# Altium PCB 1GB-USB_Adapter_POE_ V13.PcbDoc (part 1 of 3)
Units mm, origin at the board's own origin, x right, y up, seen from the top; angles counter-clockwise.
Board outline 92 x 80 mm, 4 copper layers (Top Layer, Signal Layer 2, Signal Layer 3, Bottom Layer), stack 1.57 mm thick; 189 components, 102 nets, 551 pads, 429 vias.
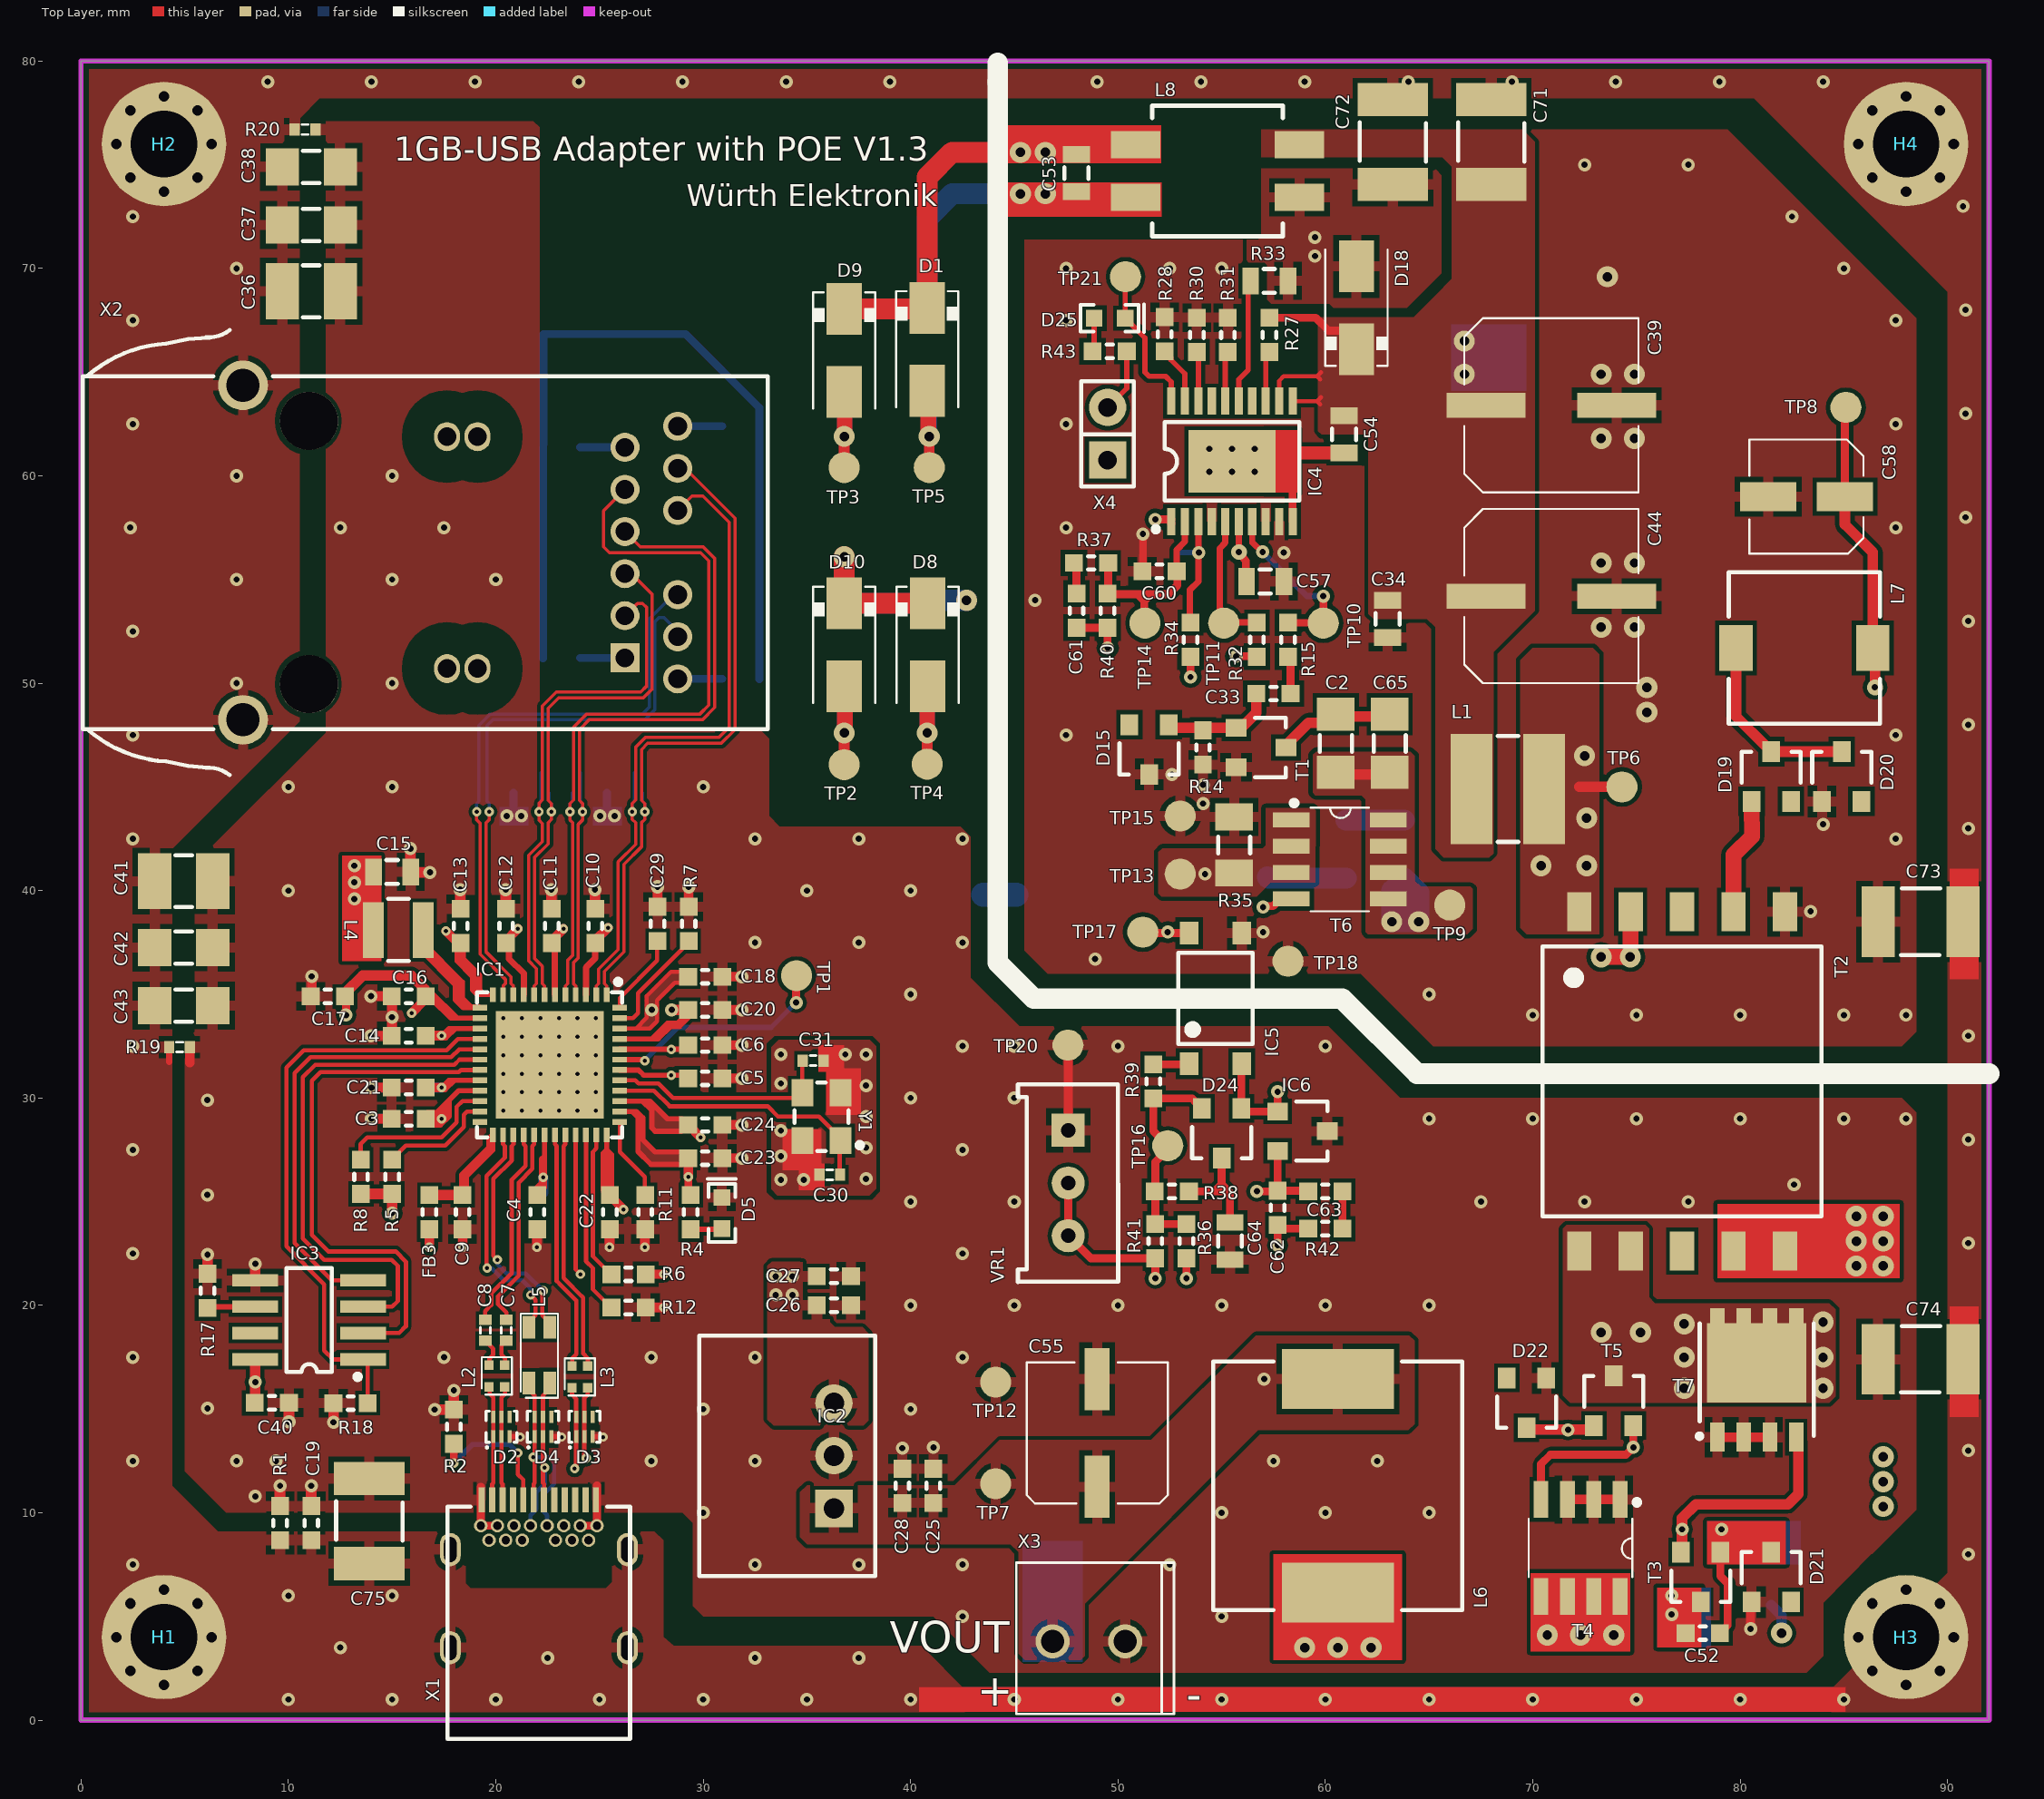
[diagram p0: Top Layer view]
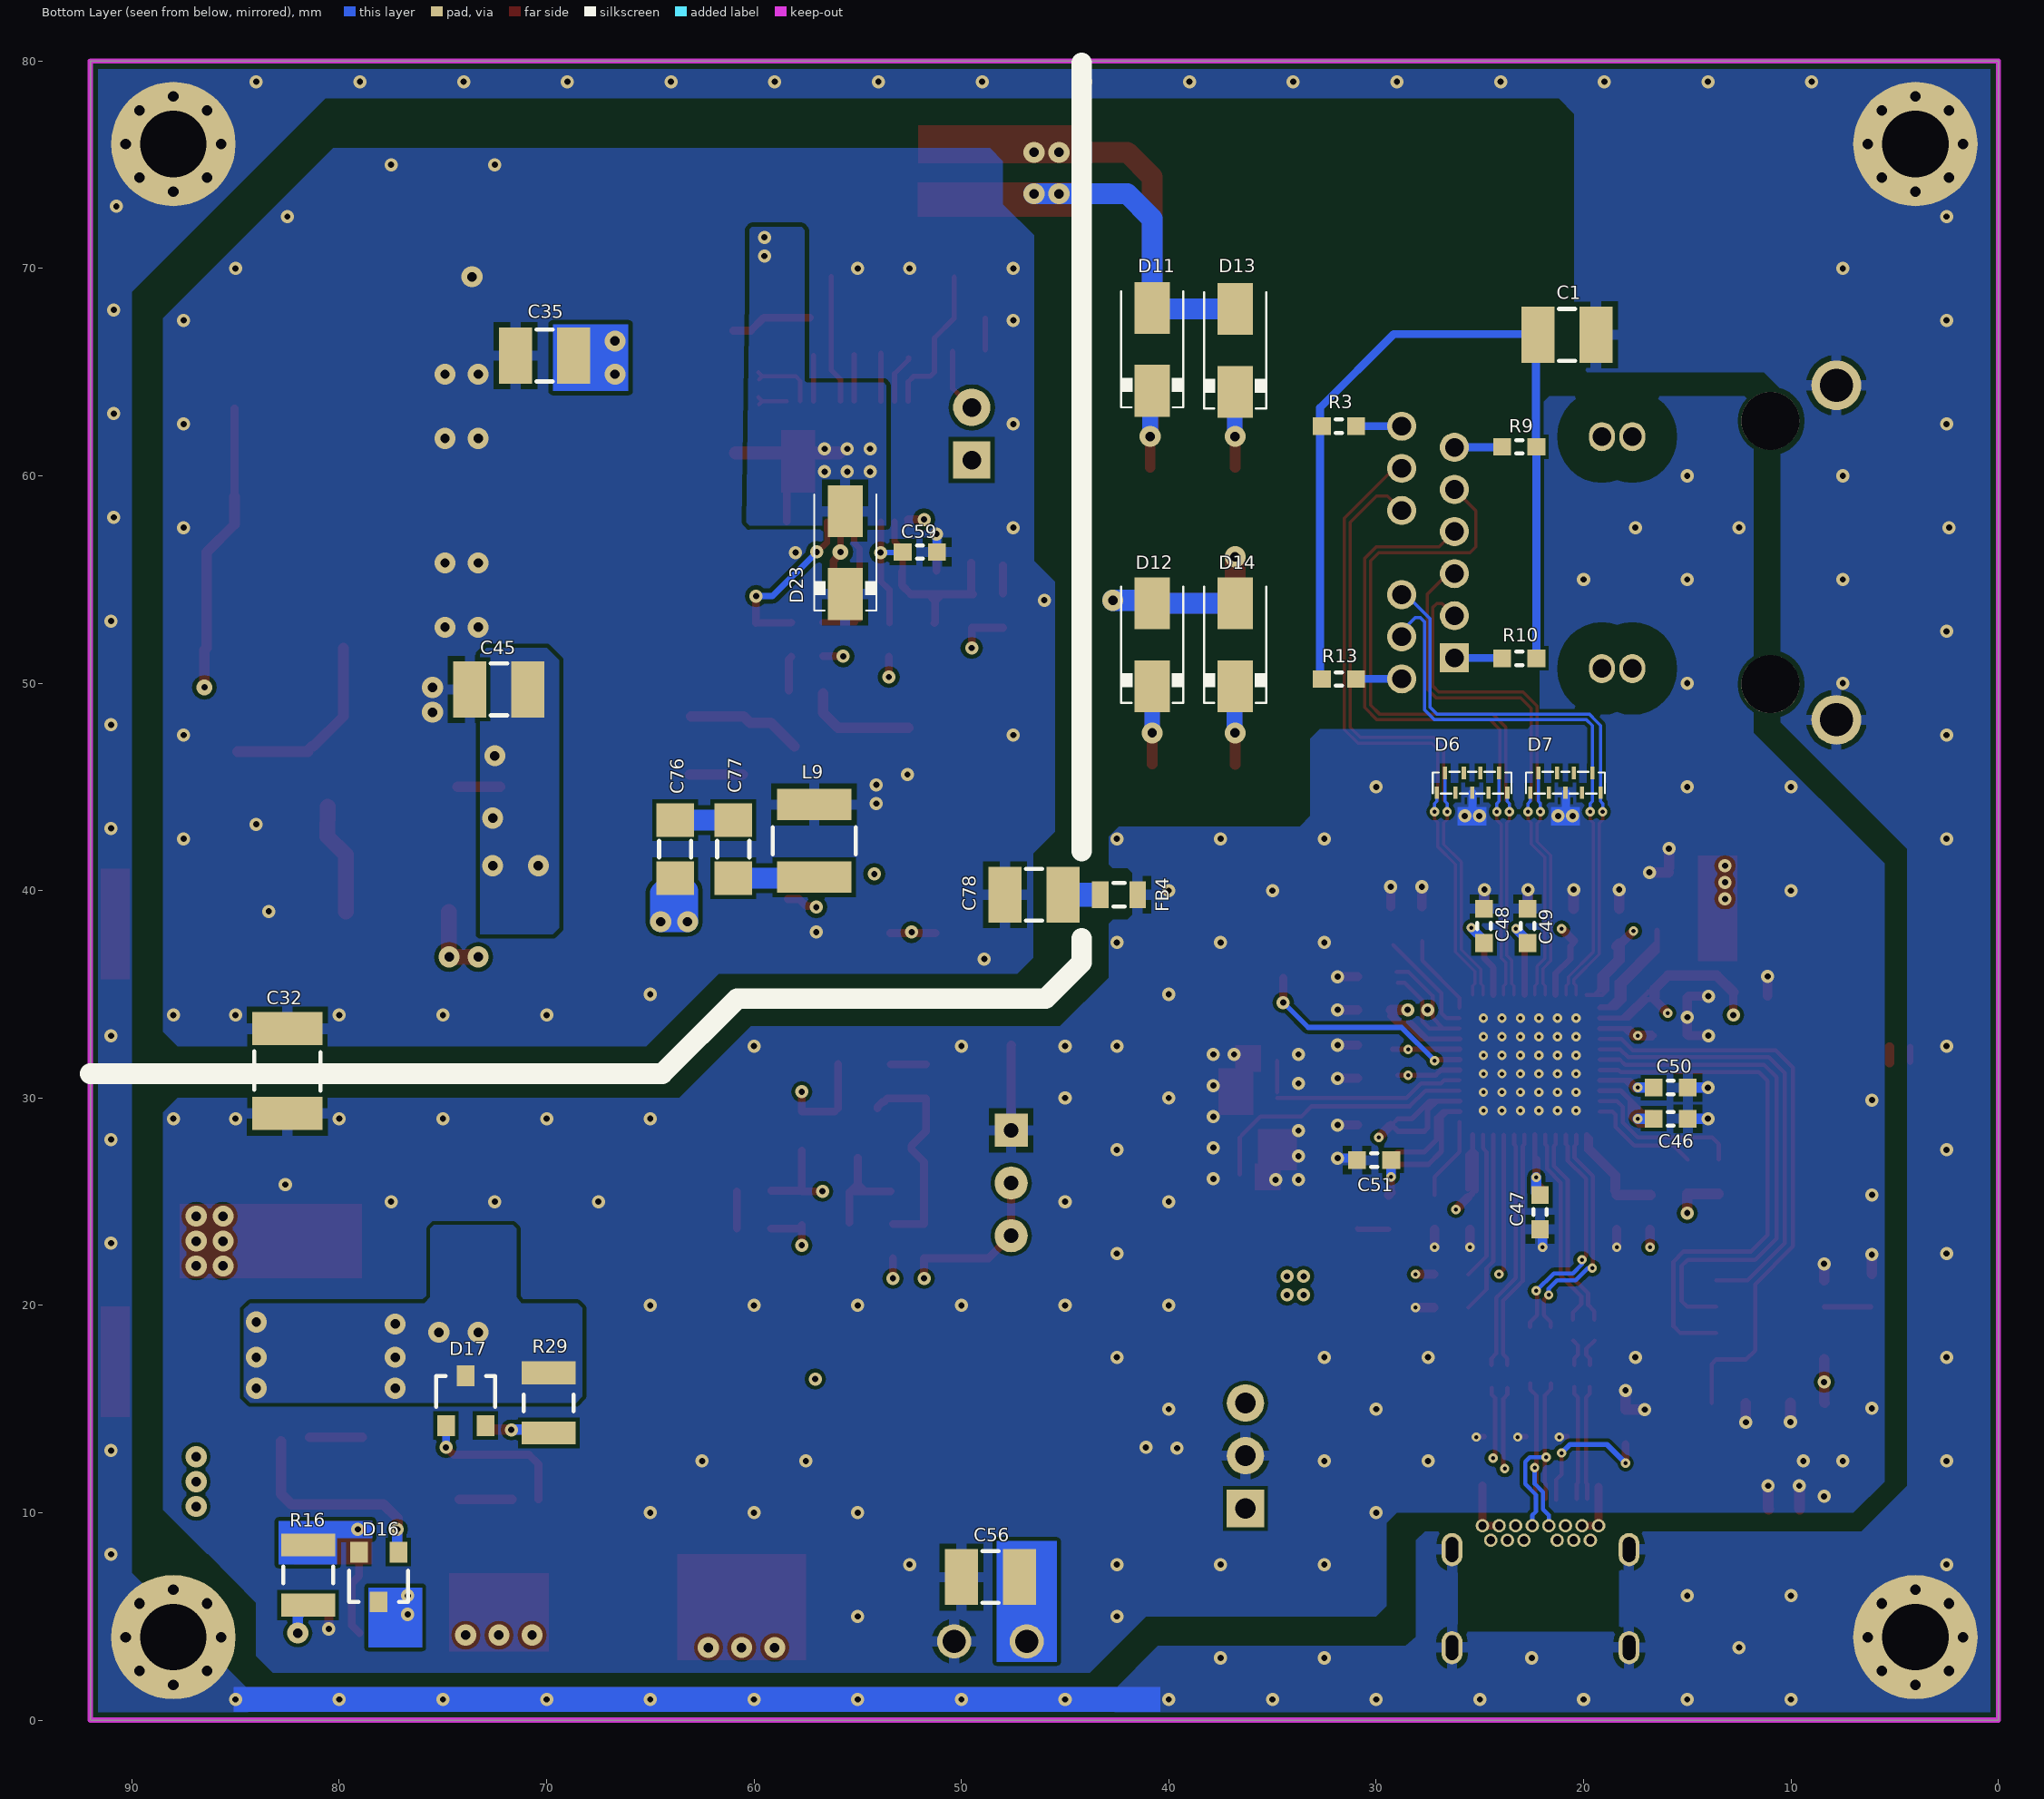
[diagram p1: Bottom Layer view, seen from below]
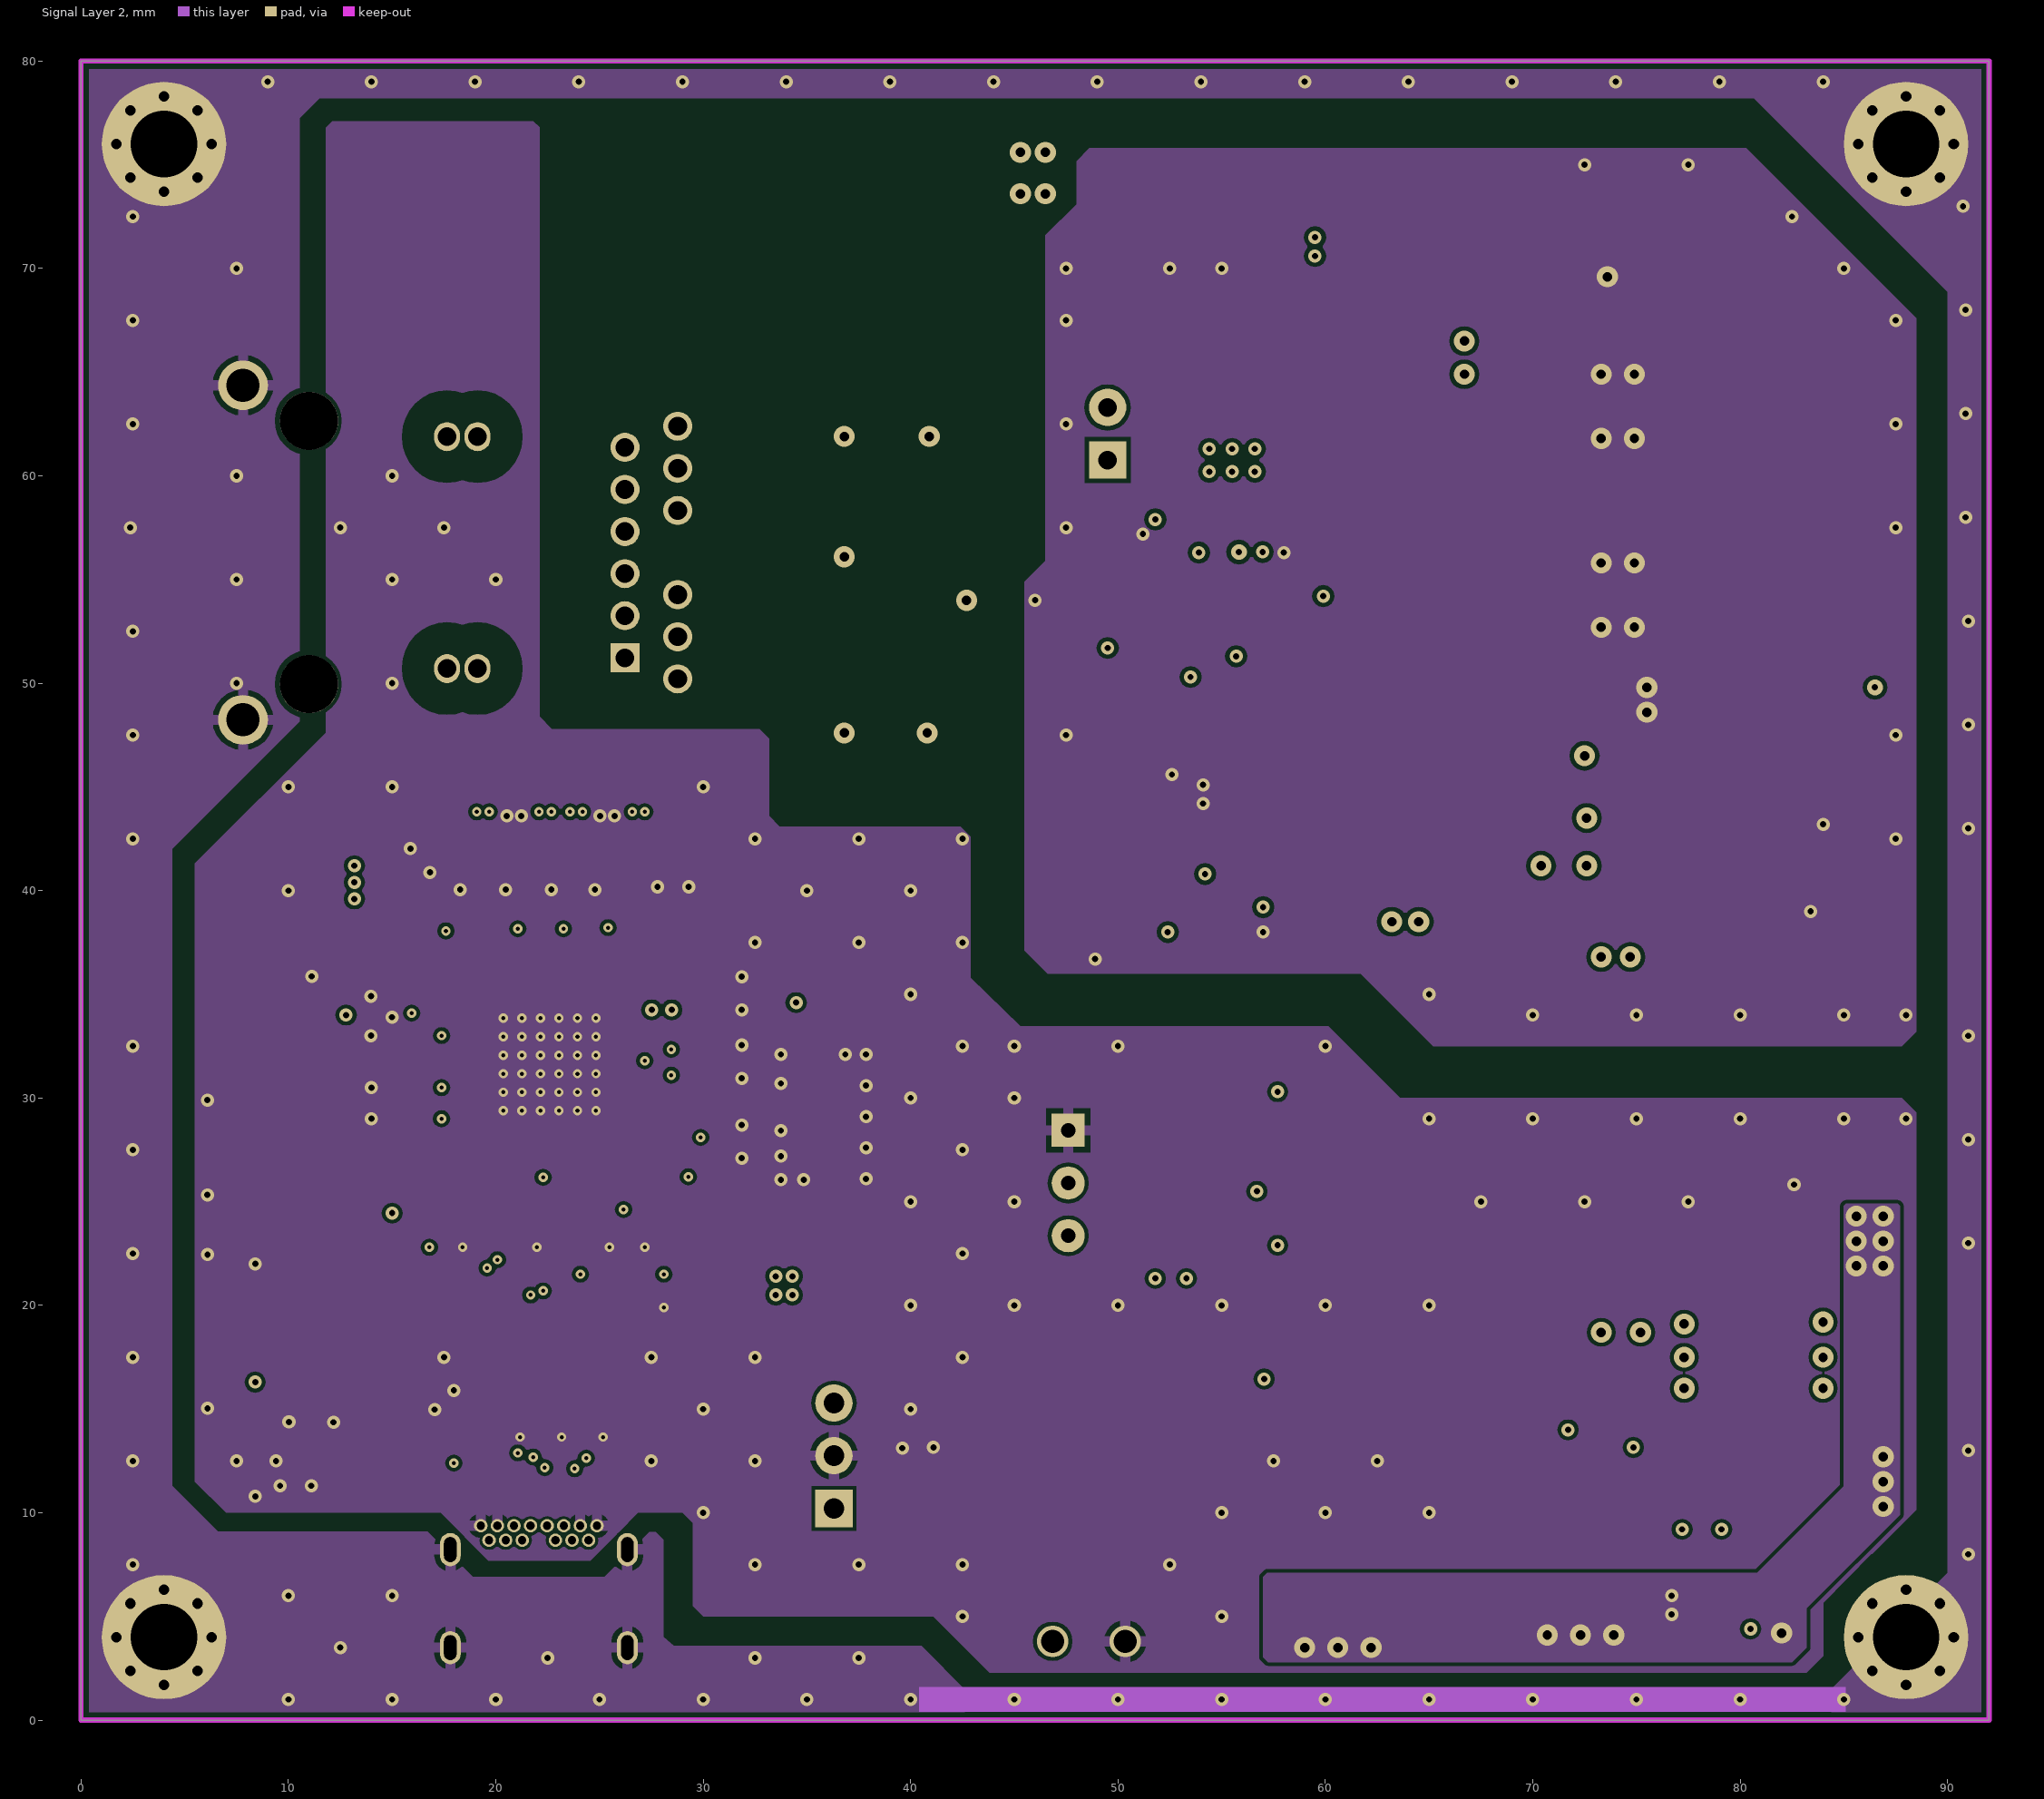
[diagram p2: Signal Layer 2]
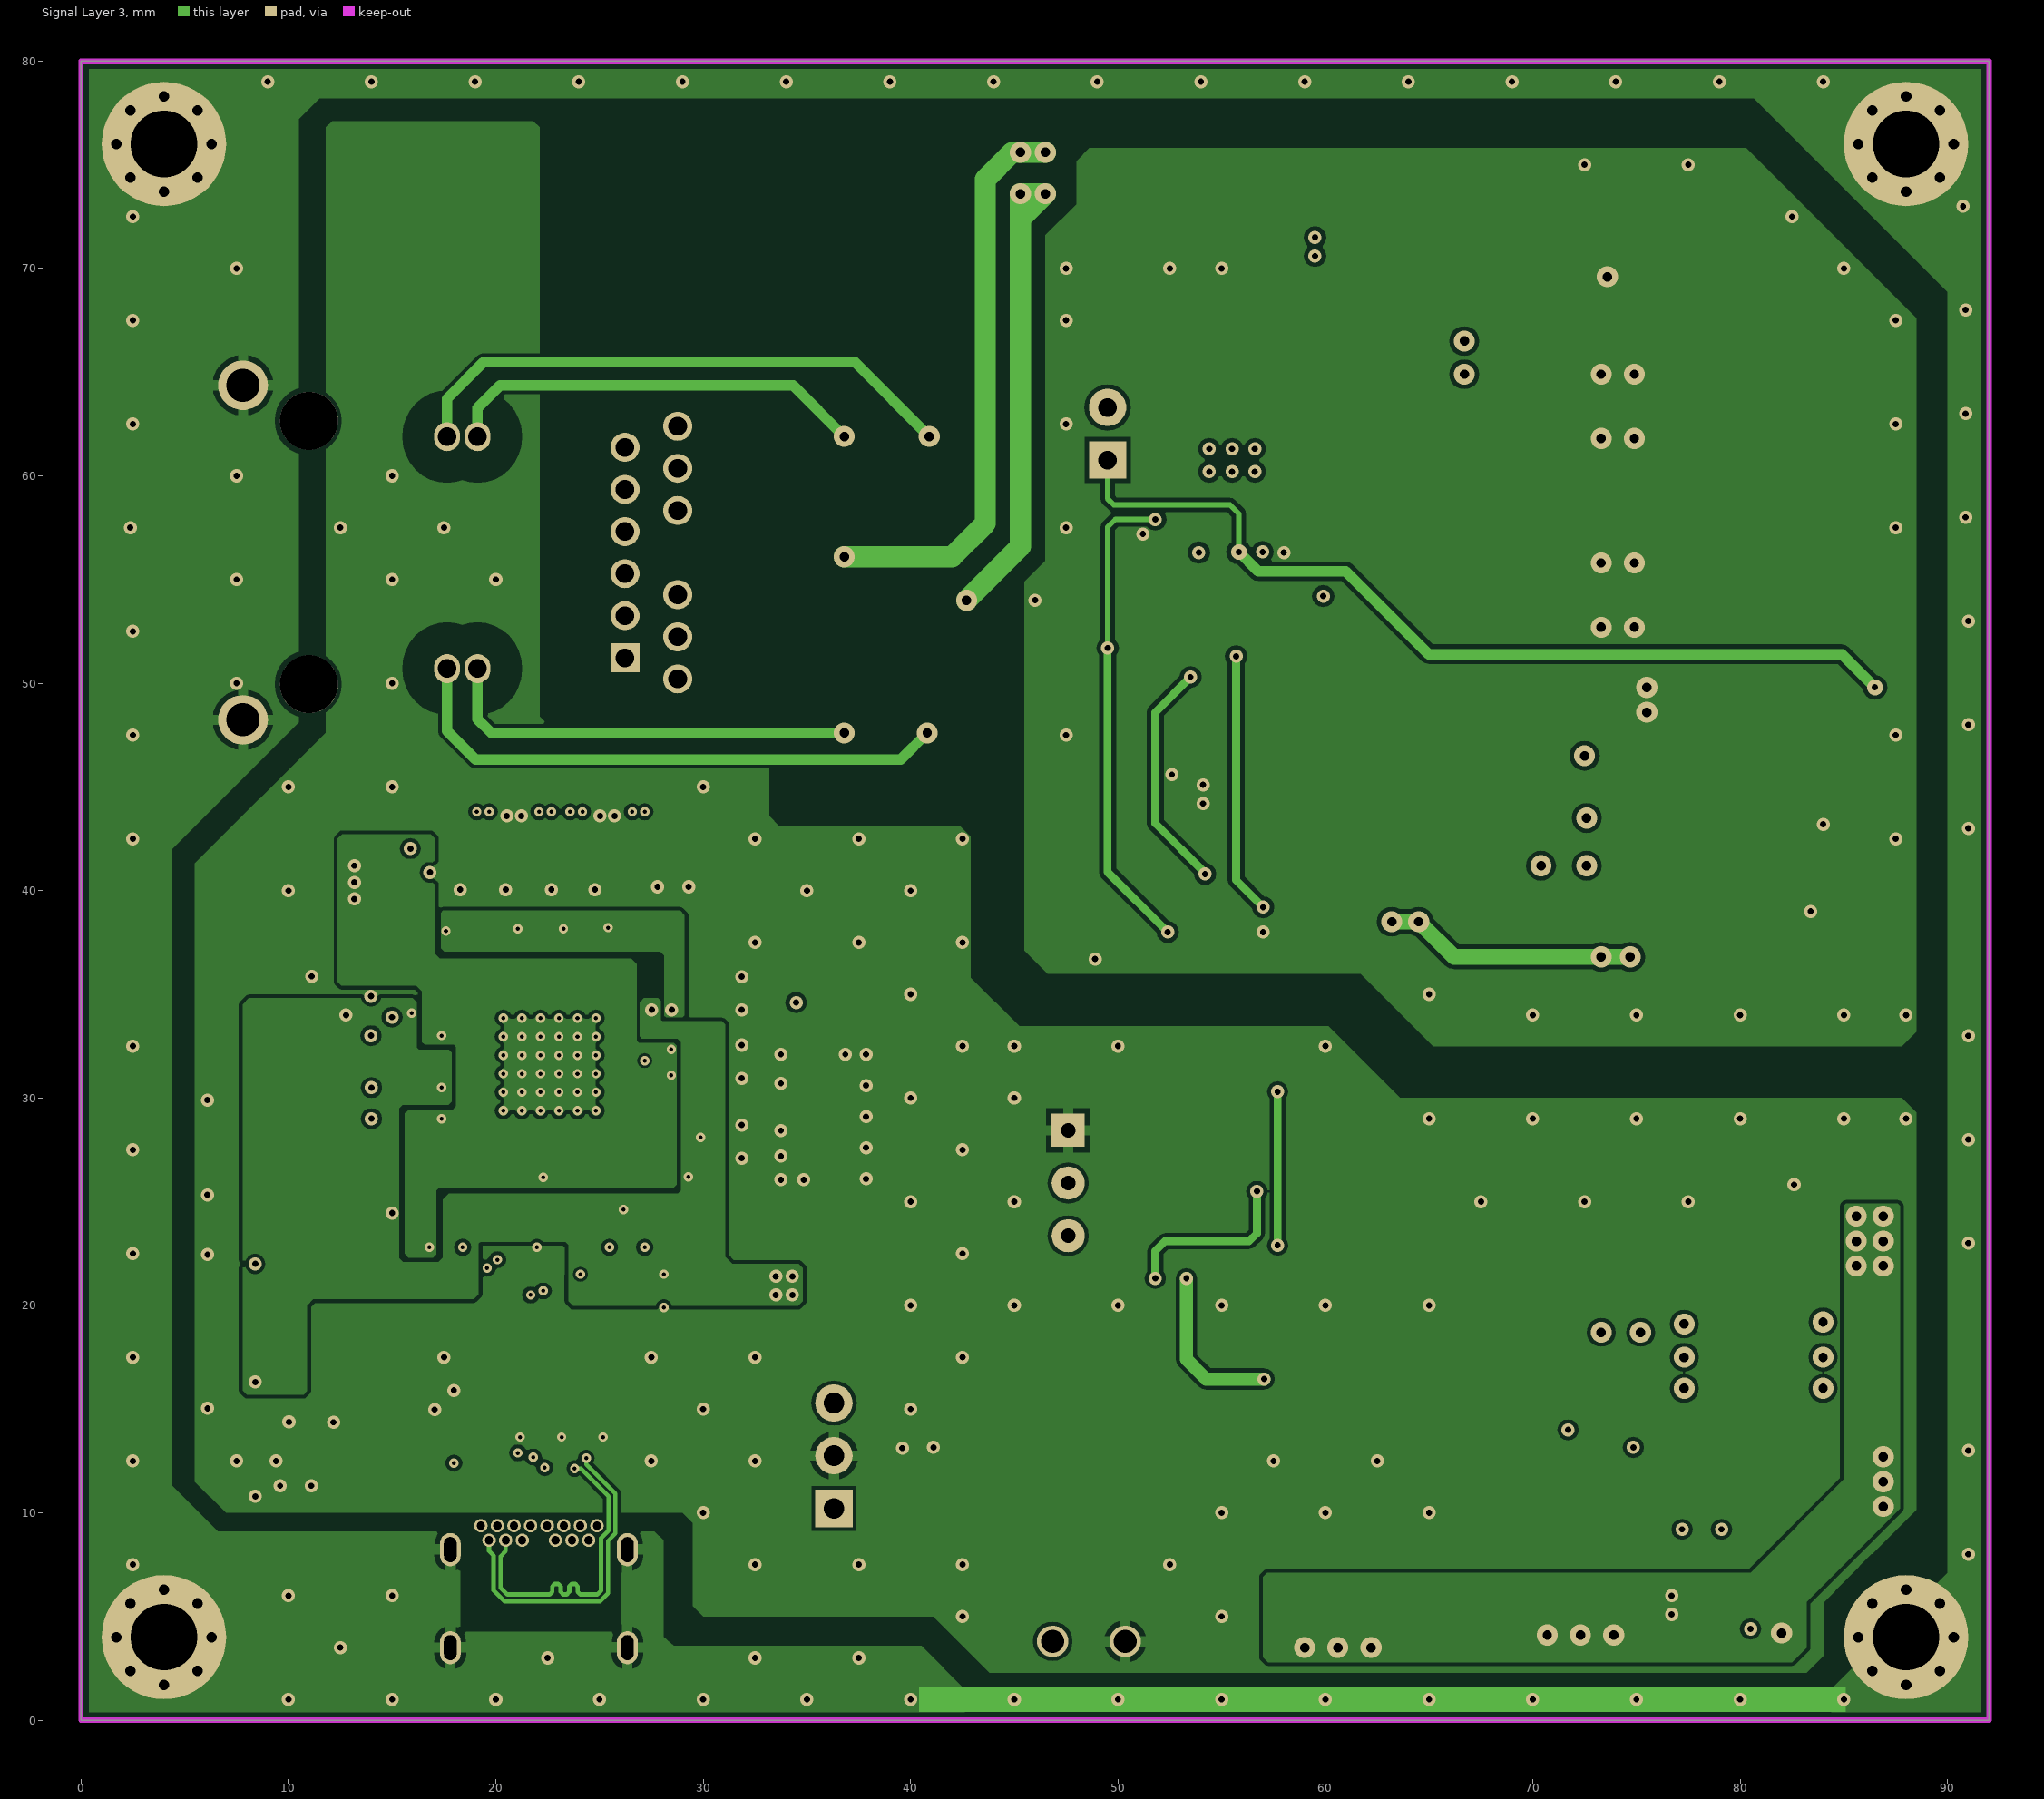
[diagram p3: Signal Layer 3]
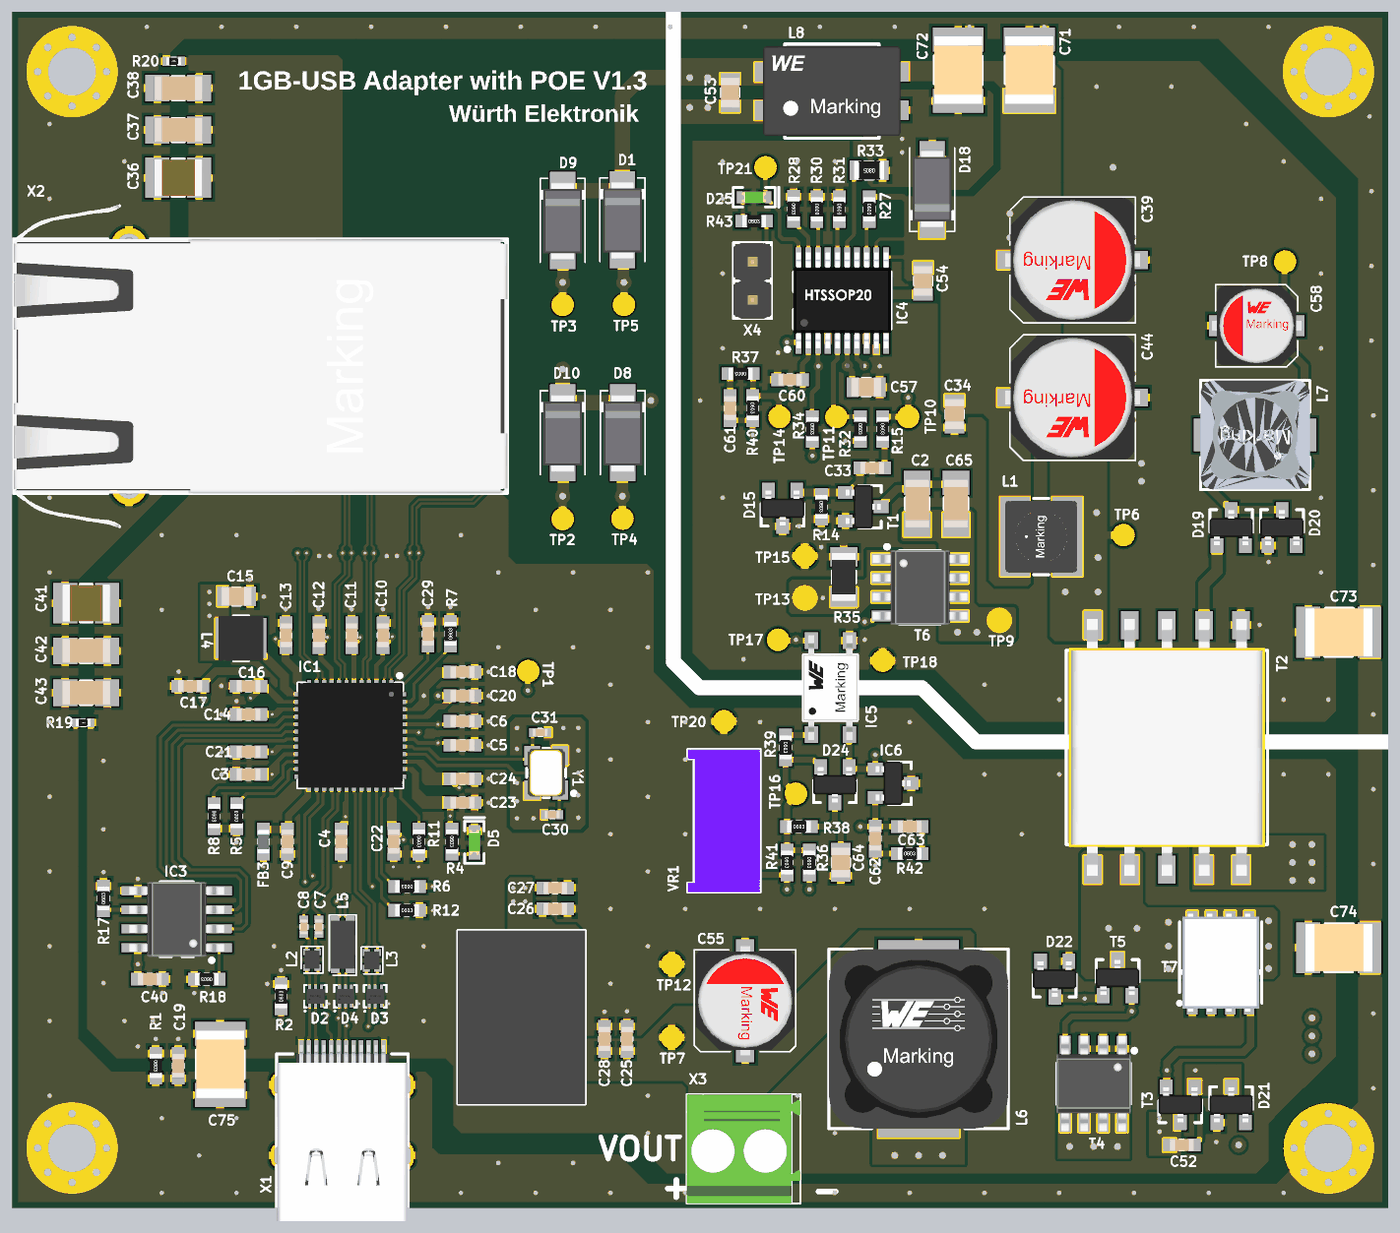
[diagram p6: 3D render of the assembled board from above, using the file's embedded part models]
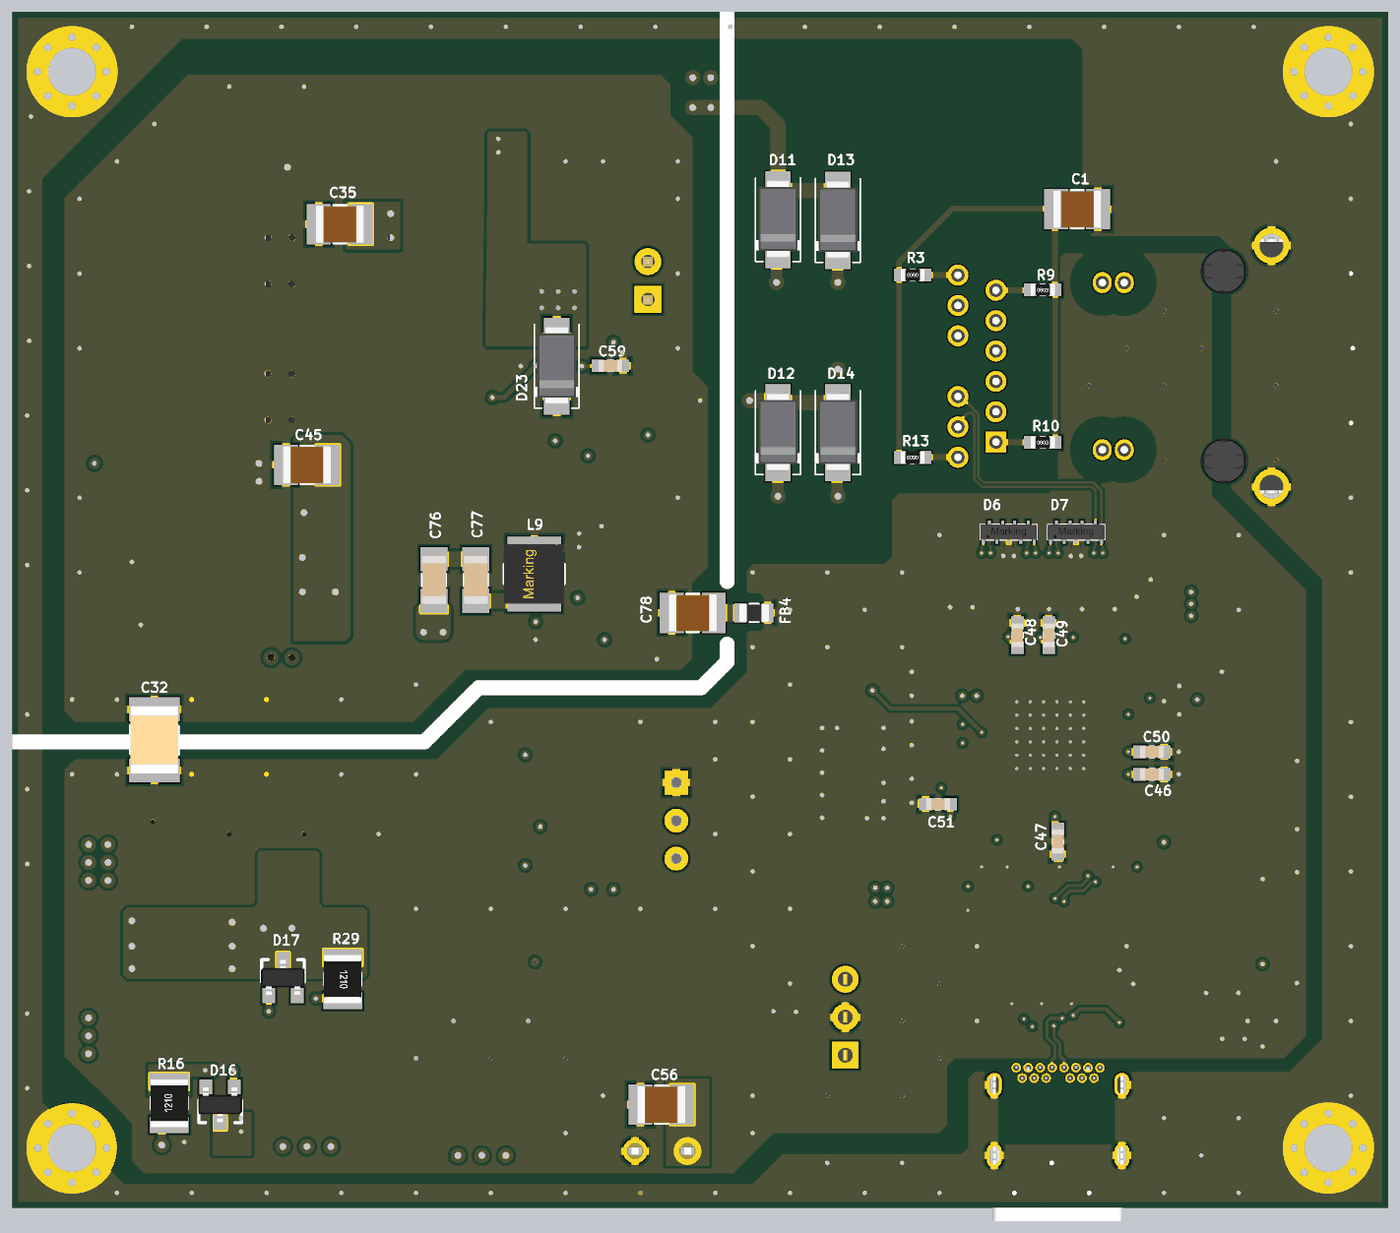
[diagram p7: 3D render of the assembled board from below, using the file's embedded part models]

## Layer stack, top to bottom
Top Solder: solder mask 0.01, Solder Resist, Dk 3.8
Top Layer: signal copper 0.035
Dielectric 1: prepreg 0.2, 7628, Dk 4.6
Signal Layer 2: signal copper 0.0175
Dielectric 3: core 1.065, Core-009, Dk 4.6
Signal Layer 3: signal copper 0.0175
Dielectric 2: prepreg 0.2, PP-006, Dk 4.6
Bottom Layer: signal copper 0.035
Bottom Solder: solder mask 0.01, Solder Resist, Dk 3.8

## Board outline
0,0 92,0 92,80 0,80

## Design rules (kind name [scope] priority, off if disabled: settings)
Clearance USB3RX1 [InNet('USB3RX1_N') vs InNet('SHIELD')] p1: gap=0.127 ignorepadtopadclearanceinfootprint=FALSE
Clearance USB-C_Pad [InPadClass('USB-C')] p2: gap=0.127 ignorepadtopadclearanceinfootprint=FALSE
Clearance PAIR_GND [InPadClass('PAIR') vs InNet('GND')] p3: gap=1.524 ignorepadtopadclearanceinfootprint=FALSE
Clearance GND [InNet('GND')] p4: gap=0.178 ignorepadtopadclearanceinfootprint=FALSE
Clearance AGND [InNet('AGND')] p5: gap=0.203 ignorepadtopadclearanceinfootprint=FALSE
Clearance SHIELD_GND [InNet('SHIELD') vs InNet('GND')] p6: gap=0.483 ignorepadtopadclearanceinfootprint=FALSE
Clearance SHIELD_ALL [InNet('SHIELD')] p7: gap=0.254 ignorepadtopadclearanceinfootprint=FALSE
Clearance Keepout [OnLayer('Keep-Out Layer')] p8: gap=0.381 ignorepadtopadclearanceinfootprint=FALSE
Clearance [All] p9: gap=0.127 ignorepadtopadclearanceinfootprint=FALSE
DiffPairsRouting DiffPairs_USB [InDifferentialPairClass('USB')] p1: maxlimit=0.254 minlimit=0.127 mostfreqgap=0.254 toplayer_maxgap=0.127 toplayer_prefgap=0.127 toplayer_minwidth=0.206 toplayer_maxwidth=0.206 toplayer_prefwidth=0.206 midlayer1_maxgap=0.127 midlayer1_prefgap=0.127 midlayer1_minwidth=0.206 midlayer1_maxwidth=0.206 midlayer1_prefwidth=0.206 midlayer2_mingap=0.254 midlayer2_minwidth=0.381 midlayer2_maxwidth=0.381 midlayer2_prefwidth=0.381 bottomlayer_maxgap=0.127 bottomlayer_prefgap=0.127 bottomlayer_minwidth=0.206 bottomlayer_maxwidth=0.206 bottomlayer_prefwidth=0.206 maxuncoupledlength=12.7
DiffPairsRouting DiffPairs_ETH [InDifferentialPairClass('ETH')] p2: maxlimit=0.254 minlimit=0.127 mostfreqgap=0.254 toplayer_maxgap=0.127 toplayer_prefgap=0.127 toplayer_minwidth=0.154 toplayer_maxwidth=0.154 toplayer_prefwidth=0.154 midlayer1_maxgap=0.127 midlayer1_prefgap=0.127 midlayer1_minwidth=0.154 midlayer1_maxwidth=0.154 midlayer1_prefwidth=0.154 midlayer2_mingap=0.254 midlayer2_minwidth=0.381 midlayer2_maxwidth=0.381 midlayer2_prefwidth=0.381 bottomlayer_maxgap=0.127 bottomlayer_prefgap=0.127 bottomlayer_minwidth=0.154 bottomlayer_maxwidth=0.154 bottomlayer_prefwidth=0.154 maxuncoupledlength=12.7
HoleSize [All] p1: absolutevalues=TRUE maxlimit=5 minlimit=0.025 maxpercent=80.000 minpercent=20.000
MinimumSolderMaskSliver [All] p1 off: minsoldermaskwidth=0.254
PlaneConnect [All] p1: pad.planeconnectstyle=Relief pad.reliefexpansion=0.508 pad.reliefentries=4 pad.reliefconductorwidth=0.381 pad.reliefairgap=0.203 via.planeconnectstyle=Direct via.reliefexpansion=0.508 via.reliefentries=4 via.reliefconductorwidth=0.254 via.reliefairgap=0.254
PolygonConnect PolygonTransformer [InNetClass('Transformer')] p1: connectstyle=Direct reliefconductorwidth=0.254 reliefentries=4 polygonreliefangle="90 Angle" airgapwidth=0.254
PolygonConnect Polygon_C2_2 [InNetClass('C2_2')] p2: thpad.connectstyle=Relief thpad.reliefconductorwidth=0.254 thpad.reliefentries=4 thpad.polygonreliefangle="90 Angle" thpad.airgapwidth=0.254 smdpad.connectstyle=Direct smdpad.reliefconductorwidth=0.254 smdpad.reliefentries=4 smdpad.polygonreliefangle="90 Angle" smdpad.airgapwidth=0.254 via.connectstyle=Direct via.reliefconductorwidth=0.254 via.reliefentries=4 via.polygonreliefangle="90 Angle" via.airgapwidth=0.254
PolygonConnect Polygon_R34_2 [InNetClass('R34_2') vs InNet('NetR34_2')] p3: thpad.connectstyle=Relief thpad.reliefconductorwidth=0.254 thpad.reliefentries=4 thpad.polygonreliefangle="90 Angle" thpad.airgapwidth=0.254 smdpad.connectstyle=Direct smdpad.reliefconductorwidth=0.254 smdpad.reliefentries=4 smdpad.polygonreliefangle="90 Angle" smdpad.airgapwidth=0.254 via.connectstyle=Direct via.reliefconductorwidth=0.254 via.reliefentries=4 via.polygonreliefangle="90 Angle" via.airgapwidth=0.254
PolygonConnect "Polygon_SHIELD_USB_Fix hole" [InPadClass('Fix_Hole') vs InNet('SHIELD_USB')] p4: thpad.connectstyle=Direct thpad.reliefconductorwidth=0.254 thpad.reliefentries=4 thpad.polygonreliefangle="90 Angle" thpad.airgapwidth=0.254 smdpad.connectstyle=Relief smdpad.reliefconductorwidth=0.508 smdpad.reliefentries=4 smdpad.polygonreliefangle="90 Angle" smdpad.airgapwidth=0.254 via.connectstyle=Direct via.reliefconductorwidth=0.254 via.reliefentries=4 via.polygonreliefangle="90 Angle" via.airgapwidth=0.254
PolygonConnect Poly_GND_OSC [InNamedPolygon('GND_OSC') vs InNet('GND')] p5: connectstyle=Direct reliefconductorwidth=0.254 reliefentries=4 polygonreliefangle="90 Angle" airgapwidth=0.254
PolygonConnect "Poly_SHIELD_Fix hole" [InPadClass('Fix_Hole') vs InNet('SHIELD')] p6: thpad.connectstyle=Direct thpad.reliefconductorwidth=0.254 thpad.reliefentries=4 thpad.polygonreliefangle="90 Angle" thpad.airgapwidth=0.254 smdpad.connectstyle=Relief smdpad.reliefconductorwidth=0.508 smdpad.reliefentries=4 smdpad.polygonreliefangle="90 Angle" smdpad.airgapwidth=0.254 via.connectstyle=Direct via.reliefconductorwidth=0.254 via.reliefentries=4 via.polygonreliefangle="90 Angle" via.airgapwidth=0.254
PolygonConnect Poly_SHIELD [All vs InNet('SHIELD')] p7: thpad.connectstyle=Relief thpad.reliefconductorwidth=0.508 thpad.reliefentries=4 thpad.polygonreliefangle="90 Angle" thpad.airgapwidth=0.254 smdpad.connectstyle=Relief smdpad.reliefconductorwidth=0.508 smdpad.reliefentries=4 smdpad.polygonreliefangle="90 Angle" smdpad.airgapwidth=0.254 via.connectstyle=Direct via.reliefconductorwidth=0.254 via.reliefentries=4 via.polygonreliefangle="90 Angle" via.airgapwidth=0.254
PolygonConnect [All] p8: thpad.connectstyle=Relief thpad.reliefconductorwidth=0.508 thpad.reliefentries=4 thpad.polygonreliefangle="90 Angle" thpad.airgapwidth=0.254 smdpad.connectstyle=Relief smdpad.reliefconductorwidth=0.508 smdpad.reliefentries=4 smdpad.polygonreliefangle="90 Angle" smdpad.airgapwidth=0.254 via.connectstyle=Direct via.reliefconductorwidth=0.254 via.reliefentries=4 via.polygonreliefangle="90 Angle" via.airgapwidth=0.254
RoutingVias [All] p1: holewidth=0.2 width=0.5 viastyle="Through Hole" minholewidth=0.2 minwidth=0.45 maxholewidth=0.711 maxwidth=1.27
SilkToSilkClearance [All] p1 off: silktosilkclearance=0.254
SilkToSolderMaskClearance [IsPad] p1 off: minsilkscreentomaskgap=0.254 clearancetoexposedcopper=TRUE
SolderMaskExpansion [All] p1: expansion=0.102
Width [All] p1: maxlimit=2.54 minlimit=0.127 preferedwidth=0.254 minimp=50.000000 maximp=50.000000 favimp=50.000000
24 further rules are at their usual default settings.

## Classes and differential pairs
pad class USB-C: X1-B1 X1-B2 X1-B3 X1-B4 X1-B5 X1-B6 X1-B7 X1-B8 X1-B9 X1-B10 X1-B11 X1-B12
pad class PAIR: X2-P13 X2-P14 X2-P15 X2-P16
net class Transformer: NetC34_1 NetC45_1 NetC52_2 NetD17_3
net class C2_2: NetC2_2
net class R34_2: NetR34_2
component class 02-POE: C2 C32 C33 C34 C35 C39 C44 C45 C52 C53 C54 C55 C56 C57 C58 C59 C60 C61 C62 C63 C64 C65 C71 C72 C73 C74 C75 C76 C77 C78 D15 D16 D17 D18 D19 D20 D21 D22 D23 D24 D25 FB4 IC4 IC5 IC6 L1 L6 L7 L8 L9 R14 R15 R16 R27 R28 R29 R30 R31 R32 R33 R34 R35 R36 R37 R38 R39 R40 R41 R42 R43 T1 T2 T3 T4 T5 T6 T7 TP6 TP7 TP8 TP9 TP10 TP11 TP12 TP13 TP14 TP15 TP16 TP17 TP18 TP20 TP21 VR1 X3 X4
pad class Fix_Hole: H1-0 H2-0 H3-0 H4-0
component class 01-USB_C: C1 C3 C4 C5 C6 C7 C8 C9 C10 C11 C12 C13 C14 C15 C16 C17 C18 C19 C20 C21 C22 C23 C24 C25 C26 C27 C28 C29 C30 C31 C36 C37 C38 C40 C41 C42 C43 C46 C47 C48 C49 C50 C51 D1 D2 D3 D4 D5 D6 D7 D8 D9 D10 D11 D12 D13 D14 FB3 H1 H2 H3 H4 IC1 IC2 IC3 L2 L3 L4 L5 R1 R2 R3 R4 R5 R6 R7 R8 R9 R10 R11 R12 R13 R17 R18 R19 R20 R21 R22 TP1 TP2 TP3 TP4 TP5 X1 X2 Y1
differential pair USB3TX: +USB3TX_P -USB3TX_N
differential pair USB3TX1: +USB3RX1_P -USB3RX1_N
differential pair USB3RX: +USB3RX_P -USB3RX_N
differential pair USB3RX1: +USB3TX1_P -USB3TX1_N
differential pair USB2D: +USB2D_P -USB2D_N
differential pair USB2D1: +USB2D1_P -USB2D1_N
differential pair TR3: +TR3_P -TR3_N
differential pair TR2: +TR2_P -TR2_N
differential pair TR1: +TR1_P -TR1_N
differential pair TR0: +TR0_P -TR0_N

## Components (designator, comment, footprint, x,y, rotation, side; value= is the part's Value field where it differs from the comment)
C1 "885342209009" CC3225-1210 20.8,66.8 r180 bottom value=1nF
C2 "885342208014" CC3216-1206 60.5,47.1 r270 top value=22nF
C3 "885012206071" CC1608-0603 15.8,29 r180 top value=100nF
C4 "885012206071" CC1608-0603 22,24.5 r270 top value=100nF
C5 "885012206071" CC1608-0603 30.1,30.95 r0 top value=100nF
C6 "885012206071" CC1608-0603 30.1,32.55 r0 top value=100nF
C7 "885012105018" CC1005-0402 20.5,18.8 r90 top value=100nF
C8 "885012105018" CC1005-0402 19.5,18.8 r90 top value=100nF
C9 "885012206052" CC1608-0603 18.4,24.5 r270 top value=1uF
C10 "885012206071" CC1608-0603 24.8,38.3 r90 top value=100nF
C11 "885012206071" CC1608-0603 22.7,38.3 r90 top value=100nF
C12 "885012206071" CC1608-0603 20.5,38.3 r90 top value=100nF
C13 "885012206071" CC1608-0603 18.3,38.3 r90 top value=100nF
C14 "885012206071" CC1608-0603 15.8,33 r180 top value=100nF
C15 "885012107005" CC2012-0805 15,40.9 r180 top value=22uF
C16 "885012206071" CC1608-0603 15.8,34.9 r180 top value=100nF
C17 "885012106006" CC1608-0603 11.9,34.9 r0 top value=10uF
C18 "885012206052" CC1608-0603 30.1,35.85 r0 top value=1uF
C19 "885012206071" CC1608-0603 11.1,9.5 r270 top value=100nF
C20 "885012206052" CC1608-0603 30.1,34.25 r0 top value=1uF
C21 "885012206071" CC1608-0603 15.8,30.5 r180 top value=100nF
C22 "885012206071" CC1608-0603 25.5,24.5 r270 top value=100nF
C23 "885012206071" CC1608-0603 30.1,27.1 r0 top value=100nF
C24 "885012206071" CC1608-0603 30.1,28.7 r0 top value=100nF
C25 "885012106018" CC1608-0603 41.1,11.3 r270 top value=2.2uF
C26 "885012106006" CC1608-0603 36.3,20 r180 top value=10uF
C27 "885012206071" CC1608-0603 36.3,21.4 r0 top value=100nF
C28 "885012206071" CC1608-0603 39.6,11.3 r90 top value=100nF
C29 "885012206052" CC1608-0603 27.8,38.4 r90 top value=1uF
C30 "885012005056" CC1005-0402 36.1,26.3 r0 top value=15pF
C31 "885012005056" CC1005-0402 35.3,31.8 r180 top value=15pF
C32 "885342210002" CC4532-1812 82.5,31.3 r270 bottom value=2.2nF
C33 "885012206052" CC1608-0603 57.5,49.5 r0 top value=1uF
C34 "885012207128" CC2012-0805 63,53.1 r270 top value=100nF
C35 "885012209069" CC3225-1210 70.1,65.8 r0 bottom value=1uF
C36 "=PartNumber" CC3225-1210 11.1,68.9 r0 top value=TBE
C37 "=PartNumber" CC3216-1206 11.1,72.1 r0 top value=TBE
C38 "=PartNumber" CC3216-1206 11.1,74.9 r0 top value=TBE
C39 "865080853006" "SMT 8mmx10mm - WE" 70.9,63.4 r90 top value=22uF
C40 "885012206071" CC1608-0603 9.2,15.3 r0 top value=100nF
C41 "=PartNumber" CC3225-1210 4.95,40.454 r0 top value=TBE
C42 "=PartNumber" CC3216-1206 4.95,37.254 r0 top value=TBE
C43 "=PartNumber" CC3216-1206 4.95,34.454 r0 top value=TBE
C44 "865080853006" "SMT 8mmx10mm - WE" 70.9,54.2 r90 top value=22uF
C45 "885012209069" CC3225-1210 72.3,49.7 r0 bottom value=1uF
C46 "885012206071" CC1608-0603 15.8,29 r180 bottom value=100nF
C47 "885012206071" CC1608-0603 22.1,24.5 r270 bottom value=100nF
C48 "885012206071" CC1608-0603 24.8,38.3 r90 bottom value=100nF
C49 "885012206071" CC1608-0603 22.7,38.3 r90 bottom value=100nF
C50 "885012206071" CC1608-0603 15.8,30.5 r180 bottom value=100nF
C51 "885012206071" CC1608-0603 30.1,27 r0 bottom value=100nF
C52 "885012206077" CC1608-0603 78.2,4.2 r180 top value=100pF
C53 "885012207116" CC2012-0805 48,74.6 r90 top value=1nF
C54 "885012207128" CC2012-0805 60.9,62 r270 top value=100nF
C55 "865230345005" "SMT 6.3mmx7.7mm - WE" 49,13.85 r180 top value=100uF
C56 "885012109014" CC3225-1210 48.6,6.9 r0 bottom value=22uF
C57 "885382207003" CC2012-0805 57.1,54.9 r0 top value=1uF
C58 "865060442002" "SMT 5mmx5.5mm - WE" 83.2,59 r270 top value=22uF
C59 "885012006055" CC1608-0603 52,56.325 r180 bottom value=47pF
C60 "885012206052" CC1608-0603 52,55.4 r180 top value=1uF
C61 "885012206091" CC1608-0603 48,53.5 r270 top value=22nF
C62 "885012006073" CC1608-0603 57.7,24.7 r90 top value=10pF
C63 "885012206090" CC1608-0603 60,25.5 r180 top value=15nF
C64 "885382207001" CC2012-0805 55.4,23.1 r270 top value=1uF
C65 "885342208014" CC3216-1206 63.1,47.1 r270 top value=22nF
C71 "885342211008" CC4532-1812 68,76.1 r90 top value=4.7nF
C72 "885342211008" CC4532-1812 63.254,76.1 r270 top value=4.7nF
C73 "885342210002" CC4532-1812 88.7,38.5 r180 top value=2.2nF
C74 "885342210002" CC4532-1812 88.7,17.4 r180 top value=2.2nF
C75 "885342210002" CC4532-1812 13.9,9.6 r90 top value=2.2nF
C76 "885012208106" CC3216-1206 63.8,42 r90 bottom value=1nF
C77 "885012208106" CC3216-1206 61,42 r270 bottom value=1nF
C78 "885342209009" CC3225-1210 46.5,39.8 r180 bottom value=1nF
D1 "B1100-13-F" SMA/DO-214AC 40.8,66.1 r90 top value=B1100
D2 "824012823" "DFN1210-6L 1.2X1.0" 20.275,14.15 r0 top
D3 "824012823" "DFN1210-6L 1.2X1.0" 24.275,14.15 r0 top
D4 "824012823" "DFN1210-6L 1.2X1.0" 22.275,14.15 r0 top
D5 "150060VS75020" "LED1608 (0603) - Green" 30.9,24.45 r270 top value=Green
D6 "824014885" WE-TVS_824014885 25.375,45.2 r180 bottom
D7 "824014885" WE-TVS_824014885 20.875,45.2 r180 bottom
D8 "B1100-13-F" SMA/DO-214AC 40.82,51.85 r90 top value=B1100
D9 "B1100-13-F" SMA/DO-214AC 36.8,66.05 r90 top value=B1100
D10 "B1100-13-F" SMA/DO-214AC 36.8,51.85 r90 top value=B1100
D11 "B1100-13-F" SMA/DO-214AC 40.8,66.1 r270 bottom value=B1100
D12 "B1100-13-F" SMA/DO-214AC 40.8,51.85 r270 bottom value=B1100
D13 "B1100-13-F" SMA/DO-214AC 36.8,66.05 r270 bottom value=B1100
D14 "B1100-13-F" SMA/DO-214AC 36.8,51.85 r270 bottom value=B1100
D15 "BAS16LT1G" SOT-23 51.5,46.8 r180 top value=BAS16
D16 "BAS16LT1G" SOT-23 78.1,6.9 r0 bottom value=BAS16
D17 "BAS16LT1G" SOT-23 73.9,15.4 r180 bottom value=BAS16
D18 "SMAJ58A-13-F" SMA/DO-214AC 61.5,68.1 r270 top value=SMAJ58A
D19 "BAS16LT1G" SOT-23 81.5,45.5 r0 top value=BAS16
D20 "BAS16LT1G" SOT-23 84.9,45.5 r0 top value=BAS16
D21 "BZX84C12LT1G" SOT-23 81.5,6.9 r0 top value=BZX84C12
D22 "BZX84C12LT1G" SOT-23 69.7,15.3 r180 top value=BZX84C12
D23 "SMAJ58A-13-F" SMA/DO-214AC 55.6,56.3 r270 bottom value=SMAJ58A
D24 "BAV99RF" SOT-23 55,28.3 r180 top
D25 "150060VS75020" "LED1608 (0603) - Green" 49.6,67.6 r180 top value=Green
FB3 "742792625" CF1608-0603 16.8,24.5 r270 top value=120R
FB4 "742792021" CF2012-0805 42.4,39.8 r180 bottom value=22R@100MHz
H1 "Hole M3 with Vias" M3_VIA 4,4 r0 top
H2 "Hole M3 with Vias" M3_VIA 4,76 r0 top
H3 "Hole M3 with Vias" M3_VIA 88,4 r0 top
H4 "Hole M3 with Vias" M3_VIA 88,76 r0 top
IC1 "LAN7800/Y9X" "QFN-48 7x7MM" 22.6,31.6 r270 top value=LAN7800
IC2 "173010378" WE_SIP-3 36.304,12.75 r90 top
IC3 "93AA66C-I/SN" SO-8N 11,19.3 r90 top
IC4 "TPS23754PWP-1" "HTSSOP-20 6.5x4.4mm" 55.5,60.7 r0 top
IC5 "140356145100" "OPTO_WL-OCPT SOP-4" 54.7,34.8 r90 top
IC6 "TL431ACDBZR" SOT-23 58.9,28.4 r270 top value=TL431AC
L1 "744043003" "Inductor_WE-TPC 4828" 68.8,44.9 r0 top value=3.3uH
L2 "7442335600" INDUCTOR_WE-CNSW-HF-0504 20.05,16.6 r90 top value="60R @ 100MHz"
L3 "7442335600" INDUCTOR_WE-CNSW-HF-0504 24.05,16.55 r90 top value="60R @ 100MHz"
L4 "74404032033" "Inductor_WE-LQS 3015" 15.3,38.1 r180 top value=3.3uH
L5 "744232090" INDUCTOR_WE-CNSW-1206 22.1,17.6 r90 top value="90R @ 100MHz"
L6 "744770122" "Inductor_WE-PD 1280" 60.6,11.3 r90 top value=22uH
L7 "74477830" "Inductor_WE-PD 7332" 83.1,51.7 r180 top value=1mH
L8 "744222" Inductor_WE-SL2 54.8,74.7 r0 top value=2x1000uH
L9 "74404042047" Inductor_WE-LQS-4018 57.1,42.4 r90 bottom value=4.7uH
R1 "RC0603FR-07330RL" CR1608-0603 9.6,9.5 r270 top value=330R
R2 "RC0603FR-075K1L" CR1608-0603 17.975,14.15 r90 top value=5k1
R3 "RC0603FR-0775RL" CR1608-0603 31.8,62.4 r0 bottom value=75R
R4 "RC0603FR-07330RL" CR1608-0603 29.4,24.5 r270 top value=330R
R5 "RC0603FR-0710KL" CR1608-0603 15,26.2 r90 top value=10k
R6 "RC0603FR-0710KL" CR1608-0603 26.4,21.5 r180 top value=10k
R7 "RC0603FR-072KL" CR1608-0603 29.3,38.4 r90 top value=2k
R8 "RC0603FR-0710KL" CR1608-0603 13.5,26.2 r270 top value=10k
R9 "RC0603FR-0775RL" CR1608-0603 23.1,61.4 r180 bottom value=75R
R10 "RC0603FR-0775RL" CR1608-0603 23.1,51.2 r180 bottom value=75R
R11 "RC0603FR-0712KL" CR1608-0603 27.2,24.5 r270 top value=12k
R12 "RC0603FR-0710KL" CR1608-0603 26.4,19.9 r0 top value=10k
R13 "RC0603FR-0775RL" CR1608-0603 31.8,50.2 r0 bottom value=75R
R14 "RC0603FR-0710KL" CR1608-0603 54.1,46.9 r270 top value=10k
R15 "RC0603FR-070RL" CR1608-0603 58.2,52.1 r270 top value=0R
R16 "RC1210FR-072KL" CR3225-1210 81.5,7 r90 bottom value=2k
R17 "RC0603FR-0710KL" CR1608-0603 6.1,20.7 r90 top value=10k
R18 "RC0603FR-0710KL" CR1608-0603 13,15.29 r180 top value=10k
R19 "RC0402FR-070RL" CR1005-0402 4.75,32.454 r0 top value=0R
R20 "RC0402FR-070RL" CR1005-0402 10.8,76.7 r0 top value=0R
R27 "RC0603FR-0724K9L" CR1608-0603 57.3,66.8 r270 top value=24k9
R28 "RC0603FR-0769K8L" CR1608-0603 52.25,66.825 r270 top value=69k8
R29 "RC1210FR-072KL" CR3225-1210 69.9,15.3 r270 bottom value=2k
R30 "RC0603FR-0780K6L" CR1608-0603 53.8,66.8 r270 top value=80k6
R31 "RC0603FR-0763K4L" CR1608-0603 55.3,66.8 r270 top value=63k4
R32 "RC0603FR-0710RL" CR1608-0603 56.7,52.1 r270 top value=10R
R33 "RC0805FR-0763R4L" CR2012-0805 57.3,69.4 r180 top value=63R4
R34 "RC0603FR-071KL" CR1608-0603 53.5,52.1 r270 top value=1k
R35 "RL1206FR-070R12L" CR3216-1206 55.6,42.2 r270 top value=0.12R
R36 "RC0603FR-0749R9L" CR1608-0603 53.3,23.1 r270 top value=49R9
R37 "RC0603FR-07348RL" CR1608-0603 48.7,55.8 r180 top value=348R
R38 "RC0603FR-0710KL" CR1608-0603 52.6,25.5 r0 top value=10k
R39 "RC0603FR-072K49L" CR1608-0603 51.7,30.8 r270 top value=2k49
R40 "RC0603FR-071K5L" CR1608-0603 49.5,53.5 r270 top value=1k5
R41 "RC0603FR-0741K2L" CR1608-0603 51.8,23.1 r270 top value=41k2
R42 "RC0603FR-0710KL" CR1608-0603 60,23.7 r0 top value=10k
R43 "RC0603JR-076K2L" CR1608-0603 49.6,66 r0 top value=6k2
T1 "SI2325DS-T1-E3" SOT-23 56.9,46.9 r270 top value=SI2325DS
T2 "750311320" WE-FB_EP13 77.2,30.8 r270 top
T3 "MMBTA06LT1G" SOT-23 78.1,6.9 r180 top value=MMBTA06
T4 "SI4850EY-T1-GE3" SO-8 72.3,8.3 r180 top value=SI4850EY
T5 "MMBTA06LT1G" SOT-23 73.9,15.4 r0 top value=MMBTA06
T6 "SI4848DY-T1-GE3" SO-8 60.7,41.5 r270 top value=SI4848DY
T7 "SI7852DP-T1-GE3" "PowerPAK SO-8" 80.8,16.4 r90 top value=SI7852DP
TP1 "=PartNumber" "TESTPOINT 1.5mm" 34.5,35.9 r270 top value=1.5mm
TP2 "=PartNumber" "TESTPOINT 1.5mm" 36.8,46.074 r0 top value=1.5mm
TP3 "=PartNumber" "TESTPOINT 1.5mm" 36.8,60.4 r0 top value=1.5mm
TP4 "=PartNumber" "TESTPOINT 1.5mm" 40.8,46.1 r0 top value=1.5mm
TP5 "=PartNumber" "TESTPOINT 1.5mm" 40.9,60.4 r0 top value=1.5mm
TP6 "=PartNumber" "TESTPOINT 1.5mm" 74.3,45 r270 top value=1.5mm
TP7 "=PartNumber" "TESTPOINT 1.5mm" 44.1,11.4 r0 top value=1.5mm
TP8 "=PartNumber" "TESTPOINT 1.5mm" 85.1,63.3 r270 top value=1.5mm
TP9 "=PartNumber" "TESTPOINT 1.5mm" 66,39.3 r270 top value=1.5mm
TP10 "=PartNumber" "TESTPOINT 1.5mm" 59.9,52.9 r270 top value=1.5mm
TP11 "=PartNumber" "TESTPOINT 1.5mm" 55.1,52.9 r270 top value=1.5mm
TP12 "=PartNumber" "TESTPOINT 1.5mm" 44.1,16.3 r0 top value=1.5mm
TP13 "=PartNumber" "TESTPOINT 1.5mm" 53,40.8 r0 top value=1.5mm
TP14 "=PartNumber" "TESTPOINT 1.5mm" 51.3,52.9 r270 top value=1.5mm
TP15 "=PartNumber" "TESTPOINT 1.5mm" 53,43.6 r0 top value=1.5mm
TP16 "=PartNumber" "TESTPOINT 1.5mm" 52.4,27.7 r0 top value=1.5mm
TP17 "=PartNumber" "TESTPOINT 1.5mm" 51.2,38 r270 top value=1.5mm
TP18 "=PartNumber" "TESTPOINT 1.5mm" 58.2,36.595 r0 top value=1.5mm
TP20 "=PartNumber" "TESTPOINT 1.5mm" 47.587,32.55 r0 top value=1.5mm
TP21 "=PartNumber" "TESTPOINT 1.5mm" 50.364,69.6 r270 top value=1.5mm
VR1 "3296W-1-203LF" 3296W 47.6,25.9 r270 top value=20k
X1 "632723300011" 632723300011_USB_TypeC 22.075,0.045 r0 top value="USB-C Receptacle"
X2 "7499511001A" RJ45_7499511001A 16.6,56.3 r270 top
X3 "691214110002S" 691214110002S 48.6,3.8 r0 top value="Screw Terminal / 2P"
X4 "61300211121" HDR1X2 49.5,60.76 r90 top value="Male Header 1x2"
Y1 "830055299" CRYSTAL_3225 35.7,29.1 r90 top value=25MHz

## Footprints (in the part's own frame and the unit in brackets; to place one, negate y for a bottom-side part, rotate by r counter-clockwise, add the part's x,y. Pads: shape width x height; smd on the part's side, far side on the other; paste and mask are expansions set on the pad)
3296W [mm]
  rect 1.6x1.6 hole 0.7: 1(-2.54,0)
  round 1.6 hole 0.7: 2(0,0) 3(2.54,0)
  silkscreen extent -4.76,-2.43 4.79,2.41, body extent -4.76,-2.43 4.79,2.4, height 11.6
632723300011_USB_TypeC [mm] "WR-COM USB 3.1 Horizontal"
  rect 0.3x1.2 smd paste+0 mask+0.064: A1(-2.75,10.58) A2(-2.25,10.58) A3(-1.75,10.58) A4(-1.25,10.58) A5(-0.75,10.58) A6(-0.25,10.58) A7(0.25,10.58) A8(0.75,10.58) A9(1.25,10.58) A10(1.75,10.58) A11(2.25,10.58) A12(2.75,10.58)
  round 0.65 hole 0.4 paste+0 mask+0.051: B1(2,9.33) B1(2.8,9.33) B2(2.4,8.63) B3(1.6,8.63) B4(1.2,9.33) B5(0.8,8.63) B6(0.4,9.33) B7(-0.4,9.33) B8(-0.8,8.63) B9(-1.2,9.33) B10(-1.6,8.63) B11(-2.4,8.63) B12(-2.8,9.33) B12(-2,9.33)
  oval 1x1.6 hole 0.6 slot 1.2 at 90 deg paste+0 mask+0.127: SH1(-4.27,3.45) SH2(-4.27,8.18) SH3(4.27,3.45) SH4(4.27,8.18)
  silkscreen extent -4.4,-0.95 4.4,10.25, body extent -4.37,-0.95 4.37,10.84, height 3.03
691214110002S [mm] "691214110002S"
  round 1.65 / inner round 1.524 / far side round 1.65 hole 1.1: 1(-1.75,0) 2(1.75,0)
  silkscreen extent -3.5,-3.5 4.1,3.8, body extent -3.5,-3.5 4.1,3.8, height 9.15
CC1005-0402 [mm]
  rect 0.5x0.6 smd mask+0.1: 1(-0.5,0) 2(0.5,0)
  silkscreen extent -0.15,-0.24 0.15,0.24, body extent -0.5,-0.25 0.5,0.25, height 0.49
CC1608-0603 [mil]
  rect 34x33.46 smd: 1(-32.5,0) 2(32.5,0)
  silkscreen extent -6,-13 6,13, body extent -31,-16 31,16, height 31
CC2012-0805 [mm]
  rect 0.8x1.3 smd: 1(-0.9,0) 2(0.9,0)
  silkscreen extent -0.28,-0.58 0.27,0.57, body extent -1,-0.63 1,0.63, height 0.59
CC3216-1206 [mm]
  rect 1.6x1.8 smd: 1(-1.4,0) 2(1.4,0)
  silkscreen extent -0.4,-0.77 0.4,0.77, body extent -1.6,-0.8 1.6,0.8, height 0.77
CC3225-1210 [mm]
  rect 1.6x2.7 smd: 1(-1.4,0) 2(1.4,0)
  silkscreen extent -0.4,-1.25 0.4,1.25, body extent -1.6,-1.25 1.6,1.25, height 2.5
CC4532-1812 [mm]
  rect 1.6x3.4 smd: 1(-2.05,0) 2(2.05,0)
  silkscreen extent -0.95,-1.6 0.95,1.6, body extent -2.31,-1.6 2.31,1.6, height 1.92
CF1608-0603 [mil]
  rect 34x33.46 smd: 1(-32.5,0) 2(32.5,0)
  silkscreen extent -6,-13 6,13, body extent -31,-16 31,16, height 37
CF2012-0805 [mm]
  rect 0.8x1.3 smd: 1(-0.9,0) 2(0.9,0)
  silkscreen extent -0.28,-0.58 0.27,0.57, body extent -1,-0.6 1,0.6, height 0.95
CR1005-0402 [mm]
  rect 0.5x0.6 smd mask+0.1: 1(-0.5,0) 2(0.5,0)
  silkscreen extent -0.15,-0.24 0.15,0.24, body extent -0.5,-0.25 0.5,0.25, height 0.35
CR1608-0603 [mil]
  rect 34x33.46 smd: 1(-32.5,0) 2(32.5,0)
  silkscreen extent -6,-13 6,13, body extent -31,-16 31,16, height 18
CR2012-0805 [mm]
  rect 0.8x1.3 smd: 1(-0.9,0) 2(0.9,0)
  silkscreen extent -0.28,-0.58 0.28,0.58, body extent -1,-0.62 1,0.63, height 0.5
CR3216-1206 [mm]
  rect 1.3x1.8 smd: 1(-1.35,0) 2(1.35,0)
  silkscreen extent -0.4,-0.77 0.4,0.78, body extent -1.6,-0.8 1.6,0.8, height 0.55
CR3225-1210 [mm]
  rect 1.1x2.6 smd: 1(-1.45,0) 2(1.45,0)
  silkscreen extent -0.4,-1.2 0.4,1.2, body extent -1.6,-1.25 1.6,1.25, height 0.6
CRYSTAL_3225 [mm] "CRYSTAL_3225"
  rect 1.3x1.05 smd: 1(-1.15,-0.925) 2(1.15,-0.925) 3(1.15,0.925) 4(-1.15,0.925)
  silkscreen extent -1.65,-1.98 1.65,1.3, body extent -1.6,-1.25 1.6,1.25, height 1.05
"DFN1210-6L 1.2X1.0" [mm]
  rect 0.2x0.6 smd mask+0.051: 1(-0.4,-0.475) 2(0,-0.475) 3(0.4,-0.475) 4(0.4,0.475) 5(0,0.475) 6(-0.4,0.475)
  silkscreen extent -0.75,-1.05 0.75,0.75, body extent -0.6,-0.5 0.6,0.5, height 0.45
HDR1X2 [mm]
  rect 1.8x1.8 hole 0.9: 1(0,0)
  round 1.8 hole 0.9: 2(2.54,0)
  silkscreen extent -1.27,-1.27 3.81,1.27, body extent -1.29,-1.27 3.79,1.27, height 8.54
"HTSSOP-20 6.5x4.4mm" [mm]
  rect 0.4x1.31 smd: 1(-2.925,-2.9) 2(-2.275,-2.9) 3(-1.625,-2.9) 4(-0.975,-2.9) 5(-0.325,-2.9) 6(0.325,-2.9) 7(0.975,-2.9) 8(1.625,-2.9) 9(2.275,-2.9) 10(2.925,-2.9) 11(2.925,2.9) 12(2.275,2.9) 13(1.625,2.9) 14(0.975,2.9) 15(0.325,2.9) 16(-0.325,2.9) 17(-0.975,2.9) 18(-1.625,2.9) 19(-2.275,2.9) 20(-2.925,2.9)
  rect 4.2x3 smd: 21(0,0)
  silkscreen extent -3.8,-3.4 3.25,1.9, body extent -3.25,-3.21 3.25,3.21, height 1
INDUCTOR_WE-CNSW-1206 [mm] "Common Mode Choke"
  rect 1.1x0.6 smd: 1(-1.35,0.5) 2(1.35,0.5) 3(1.35,-0.5) 4(-1.35,-0.5)
  silkscreen extent -2.05,-0.9 2,0.9, body extent -1.6,-0.8 1.6,0.8, height 1.8
INDUCTOR_WE-CNSW-HF-0504 [mm] "Common Mode Choke"
  rect 0.45x0.45 smd: 1(-0.525,0.375) 2(0.525,0.375) 3(0.525,-0.375) 4(-0.525,-0.375)
  silkscreen extent -0.9,-0.72 0.9,0.73, body extent -0.6,-0.5 0.6,0.5, height 0.9
"Inductor_WE-LQS 3015" [mm] "WE-LQS SMT Power Inductor"
  rect 1x2.7 smd: 1(-1.2,0) 2(1.2,0)
  silkscreen extent -0.5,-1.5 0.5,1.5, body extent -1.5,-1.5 1.5,1.5, height 1.5
Inductor_WE-LQS-4018 [mm]
  rect 1.5x3.6 smd: 1(-1.75,0) 2(1.75,0)
  silkscreen extent -0.65,-2 0.65,2, body extent -2,-2 2,2, height 1.9
"Inductor_WE-PD 1280" [mm] "WE-PD SMD Shielded Power Inductor"
  rect 2.9x5.4 smd: 1(-5.15,0) 2(5.15,0)
  silkscreen extent -6,-6 6,6, body extent -6,-6 6,6, height 7.26
"Inductor_WE-PD 7332" [mm] "WE-PD SMT Power  Inductor"
  rect 1.6x2.2 smd: 1(-3.3,0) 2(3.3,0)
  silkscreen extent -3.65,-3.65 3.65,3.65, body extent -3.65,-3.65 3.65,3.65, height 3.6
Inductor_WE-SL2 [mm] "WE-SL2 SMD Common Mode Line  Filter"
  rect 2.4x1.3 smd: 1(-3.95,-1.27) 2(-3.95,1.27) 3(3.95,1.27) 4(3.95,-1.27)
  silkscreen extent -3.15,-3.15 3.15,3.15, body extent -4.6,-3 4.6,3, height 5
"Inductor_WE-TPC 4828" [mm] "WE-TPC SMD Shielded Tiny Power  Inductor"
  rect 2x5.3 smd: 1(-1.75,0) 2(1.75,0)
  silkscreen extent -0.5,-2.55 0.5,2.55, body extent -2.4,-2.4 2.4,2.4, height 2.8
"LED1608 (0603) - Green" [mm]
  rect 0.8x0.8 smd: 1(-0.75,0) 2(0.75,0)
  silkscreen extent -1.65,-0.67 1.4,0.67, body extent -0.81,-0.4 0.81,0.4, height 0.6
M3_VIA [mm]
  round 6 hole 3.2 mask+0.05: 0(0,0)
"OPTO_WL-OCPT SOP-4" [mm]
  rect 1.1x0.9 smd: 1(-3.15,1.27) 2(-3.15,-1.27) 3(3.15,-1.27) 4(3.15,1.27)
  silkscreen extent -2.2,-1.8 2.2,1.8, body extent -3.5,-1.8 3.5,1.8, height 2.1
"PowerPAK SO-8" [mm]
  rect 1.4x0.7 smd: 1(-2.758,1.905) 2(-2.758,0.635) 3(-2.758,-0.635) 4(-2.758,-1.905) 5(2.757,-1.905) 6(2.757,-0.635) 7(2.757,0.635) 8(2.757,1.905)
  rect 3.81x4.8 smd: 9(0.827,0)
  silkscreen extent -2.81,-2.75 2.72,2.86, body extent -3.28,-2.7 3.27,2.7, height 1.12
"QFN-48 7x7MM" [mm] "QFN, 48-Leads, Body 7x7mm (max), Pitch 0.50mm, IPC Medium Density"
  rect 0.7x0.28 smd mask+0.076: 1(-3.375,2.75) 2(-3.375,2.25) 3(-3.375,1.75) 4(-3.375,1.25) 5(-3.375,0.75) 6(-3.375,0.25) 7(-3.375,-0.25) 8(-3.375,-0.75) 9(-3.375,-1.25) 10(-3.375,-1.75) 11(-3.375,-2.25) 12(-3.375,-2.75) 25(3.375,-2.75) 26(3.375,-2.25) 27(3.375,-1.75) 28(3.375,-1.25) 29(3.375,-0.75) 30(3.375,-0.25) 31(3.375,0.25) 32(3.375,0.75) 33(3.375,1.25) 34(3.375,1.75) 35(3.375,2.25) 36(3.375,2.75)
  rect 0.28x0.7 smd mask+0.076: 13(-2.75,-3.375) 14(-2.25,-3.375) 15(-1.75,-3.375) 16(-1.25,-3.375) 17(-0.75,-3.375) 18(-0.25,-3.375) 19(0.25,-3.375) 20(0.75,-3.375) 21(1.25,-3.375) 22(1.75,-3.375) 23(2.25,-3.375) 24(2.75,-3.375) 37(2.75,3.375) 38(2.25,3.375) 39(1.75,3.375) 40(1.25,3.375) 41(0.75,3.375) 42(0.25,3.375) 43(-0.25,3.375) 44(-0.75,3.375) 45(-1.25,3.375) 46(-1.75,3.375) 47(-2.25,3.375) 48(-2.75,3.375)
  rect 5.2x5.2 smd mask+0.076: 49(0,0)
  silkscreen extent -4.12,-3.5 3.5,3.5, body extent -3.51,-3.51 3.51,3.51, height 0.78
RJ45_7499511001A [mm] "LAN Transformer, body 33.02x17.02mm"
  round 2.8 hole 2.8 unplated: MH1(-6.35,-5.61) MH2(6.35,-5.61)
  rect 1.4x1.4 hole 0.9: P1(5.075,9.63)
  round 1.4 hole 0.9: P2(3.045,9.63) P3(1.015,9.63) P4(-1.015,9.63) P5(-3.045,9.63) P6(-5.075,9.63) P7(6.09,12.17) P8(4.06,12.17) P9(2.03,12.17) P10(-2.03,12.17) P11(-4.06,12.17) P12(-6.09,12.17)
  oval 1.4x1.25 hole 0.9: P13(5.59,2.52) P14(-5.59,2.52) P15(5.59,1.05) P16(-5.59,1.05)
  round 2.4 hole 1.6: S1(-8.065,-8.79) S2(8.065,-8.79)
  silkscreen extent -10.73,-16.51 10.73,16.51, body extent -10.81,-16.51 10.81,16.51, height 16.21
SMA/DO-214AC [mm]
  rect 2.5x1.7 smd: 1(-2,0) 2(2,0)
  silkscreen extent -2.8,-1.5 2.8,1.5, body extent -2.65,-1.3 2.55,1.3, height 2.4
"SMT 5mmx5.5mm - WE" [mm]
  rect 1.4x2.7 smd: 1(0,1.85) 2(0,-1.85)
  silkscreen extent -2.75,-2.75 2.75,2.75, body extent -2.65,-3 2.65,3, height 5.5
"SMT 6.3mmx7.7mm - WE" [mm]
  rect 1.2x3 smd: 1(0,2.6) 2(0,-2.6)
  silkscreen extent -3.4,-3.4 3.4,3.4, body extent -3.3,-3.65 3.3,3.65, height 7.7
"SMT 8mmx10mm - WE" [mm] "D=8mmxL=10.5mm"
  rect 1.2x3.8 smd: 1(0,3.15) 2(0,-3.15)
  silkscreen extent -4.2,-4.2 4.2,4.2, body extent -4.15,-4.5 4.15,4.5, height 10.5
SO-8 [mm]
  rect 0.72x1.78 smd: 1(-1.905,-2.34) 2(-0.635,-2.34) 3(0.635,-2.34) 4(1.905,-2.34) 5(1.905,2.34) 6(0.635,2.34) 7(-0.635,2.34) 8(-1.905,2.34)
  silkscreen extent -2.73,-2.22 2.5,1.4, body extent -2.5,-3.17 2.5,3.17, height 1.88
SO-8N [mm]
  rect 0.6x2.2 smd: 1(-1.905,-2.6) 2(-0.635,-2.6) 3(0.635,-2.6) 4(1.905,-2.6) 5(1.905,2.6) 6(0.635,2.6) 7(-0.635,2.6) 8(-1.905,2.6)
  silkscreen extent -2.87,-2.46 2.5,1.1, body extent -2.5,-3.17 2.5,3.17, height 1.88
SOT-23 [mm]
  rect 0.85x1 smd: 1(-0.95,-1.2) 2(0.95,-1.2) 3(0,1.2)
  silkscreen extent -1.43,-0.3 1.43,1.2, body extent -1.46,-1.17 1.46,1.17, height 1
"TESTPOINT 1.5mm" [mm]
  round 1.5 smd paste-1.5: 1(0,0)
WE-FB_EP13 [mm] "Flyback Transformer, size EP13"
  rect 1.88x1.17 smd: 1(-8.18,-4.96) 2(-8.18,-2.48) 3(-8.18,0) 4(-8.18,2.48) 5(-8.18,4.96) 6(8.18,4.96) 7(8.18,2.48) 8(8.18,0) 9(8.18,-2.48) 10(8.18,-4.96)
  silkscreen extent -6.5,-6.73 6.5,6.73, body extent -8.58,-6.56 8.58,6.56, height 11.96
WE-TVS_824014885 [mm] "ESD Suppressors / TVS Diodes"
  rect 0.2x0.6 smd paste+0: 1(-1.7,-0.475) 2(-0.8,-0.475) 3(0,-0.475) 4(0.8,-0.475) 5(1.7,-0.475) 6(1.3,0.475) 7(0.4,0.475) 8(-0.4,0.475) 9(-1.3,0.475)
  silkscreen extent -1.9,-0.53 1.9,0.53, body extent -1.9,-0.5 1.9,0.5, height 0.5
WE_SIP-3 [mm]
  rect 1.8x1.8 hole 1: 1(-2.54,0)
  round 1.8 hole 1: 2(0,0) 3(2.54,0)
  silkscreen extent -5.8,-2 5.8,6.5, body extent -5.8,-2 5.8,6.5, height 10.55

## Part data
C1: "CAP, CERM, 1nF, 2kV, +/-10%, X7R, 1210", Dielectric=X7R, Manufacturer=Wurth, Supplier Part Number 1=732-12130-1-ND, Tolerance_%=10%
C2 C65: "CAP, CERM, 22nF, 630V, +/-10%, X7R, 1206", Dielectric=X7R, Manufacturer=Wurth, Supplier Part Number 1=710-885342208014, Tolerance_%=10
C3 C4 C5 C6 C10 C11 C12 C13 C14 C16 C19 C21 C22 C23 C24 C27 C28 C40 C46 C47 C48 C49 C50 C51: "CAP, CERM, 100nF, 25V, +/-10%, X7R, 0603", Dielectric=X7R, Manufacturer=Wurth, Supplier Part Number 1=710-885012206071, Tolerance_%=10
C7 C8: "CAP, CERM, 100nF, 25V, +/-20%, X5R, 0402", Dielectric=X5R, Manufacturer=Wurth, Supplier Part Number 1=710-885012105018, Tolerance_%=20
C9 C18 C20 C29 C33 C60: "CAP, CERM, 1uF, 16V, +/-10%, X7R, 0603", Dielectric=X7R, Manufacturer=Wurth, Supplier Part Number 1=710-885012206052, Tolerance_%=10%
C15: "CAP, CERM, 22uF, 6.3V, +/-20%, X5R, 0805", Dielectric=X5R, Manufacturer=Wurth, Supplier Part Number 1=710-885012107005, Tolerance_%=20
C17 C26: "CAP, CERM, 10uF, 6.3V, +/-20%, X5R, 0603", Dielectric=X5R, Manufacturer=Wurth, Supplier Part Number 1=710-885012106006, Tolerance_%=10
C25: "CAP, CERM, 2.2uF, 16V, +/-20%, X5R, 0603", Dielectric=X5R, Manufacturer=Wurth, Supplier Part Number 1=710-885012106018, Tolerance_%=20%
C30 C31: "CAP, CERM, 15pF, 50V, +/-5%, C0G, 0402", Dielectric=C0G, Manufacturer=Wurth, Supplier Part Number 1=732-7470-1-ND, Tolerance_%=5
C32 C73 C74 C75: "CAP, CERM, 2.2nF, 2kV, +/-10%, X7R, 1812", Dielectric=X7R, Manufacturer=Wurth, Supplier Part Number 1=710-885342210002, Tolerance_%=10
C34 C54: "CAP, CERM, 100nF, 100V, +/-10%, X7R, 0805", Dielectric=X7R, Manufacturer=Wurth, Supplier Part Number 1=710-885012207128, Tolerance_%=10
C35 C45: "CAP, CERM, 1uF, 100V, +/-10%, X7R, 1210", Dielectric=X7R, Manufacturer=Wurth, Supplier Part Number 1=710-885012209069, Tolerance_%=10%
C36 C41: library part TBE_CAP_1210, "CAP, CERM, TBE, 1210"
C37 C38 C42 C43: library part TBE_CAP_1206, "CAP, CERM, TBE, 1206"
C39 C44: "CAP, ECAP, 22uF, 100V, +/-20%, 8mm x 10.5mm", Dielectric=-, Manufacturer=Wurth, Supplier Part Number 1=710-865080853006, Tolerance_%=20
C52: "CAP, CERM, 100pF, 50V, +/-10%, X7R, 0603", Dielectric=X7R, Manufacturer=Wurth, Supplier Part Number 1=710-885012206077, Tolerance_%=1
C53: "CAP, CERM, 1nF, 100V, +/-10%, X7R, 0805", Dielectric=X7R, Manufacturer=Wurth, Supplier Part Number 1=710-885012207116, Tolerance_%=10
C55: "CAP, ECAP, 100uF, 16V, +/-20%, 6.3mm x 7.7mm", Dielectric=-, Manufacturer=Wurth, Supplier Part Number 1=710-865230345005, Tolerance_%=20
C56: "CAP, CERM, 22uF, 25V, +/-20%, X5R, 1210", Dielectric=X5R, Manufacturer=Wurth, Supplier Part Number 1=732-7385-1-ND, Tolerance_%=20%
C57: "CAP, CERM, 1uF, 25V, +/-10%, X7R, 0805", Dielectric=X7R, Manufacturer=Wurth, Supplier Part Number 1=710-885382207003, Tolerance_%=10
C58: "CAP, ECAP, 22uF, 25V, +/-20%, 5mm x 5.5mm", Dielectric=-, Manufacturer=Wurth, Supplier Part Number 1=710-865060442002, Tolerance_%=20
C59: "CAP, CERM, 47pF, 50V, +/-5%, C0G, 0603", Dielectric=C0G, Manufacturer=Wurth, Supplier Part Number 1=710-885012006055, Tolerance_%=5%
C61: "CAP, CERM, 22nF, 50V, +/-10%, X7R, 0603", Dielectric=X7R, Manufacturer=Wurth, Supplier Part Number 1=710-885012206091, Tolerance_%=10%
C62: "CAP, CERM, 10pF, 100V, +/-5%, C0G, 0603", Dielectric=C0G, Manufacturer=Wurth, Supplier Part Number 1=710-885012006073, Tolerance_%=5
C63: "CAP, CERM, 15nF, 50V, +/-10%, X7R, 0603", Dielectric=X7R, Manufacturer=Wurth, Supplier Part Number 1=710-885012206090, Tolerance_%=10%
C64: "CAP, CERM, 1uF, 16V, +/-10%, X7R, 0805", Dielectric=X7R, Manufacturer=Wurth, Supplier Part Number 1=710-885382207001, Tolerance_%=10
C71 C72: "CAP, CERM, 4.7nF, 2kV, +/-10%, X7R, 1812", Dielectric=X7R, Manufacturer=Wurth, Supplier Part Number 1=710-885342211008, Tolerance_%=10
C76 C77: "CAP, CERM, 1nF, 100V, +/-10%, X7R, 1206", Dielectric=X7R, Manufacturer=Wurth, Supplier Part Number 1=710-885012208106, Tolerance_%=10
C78: "CAP, CERM, 1nF, 2kV, +/-10%, X7R, 1210", Dielectric=X7R, Manufacturer=Wurth, Supplier Part Number 1=710-885342209009, Tolerance_%=10%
